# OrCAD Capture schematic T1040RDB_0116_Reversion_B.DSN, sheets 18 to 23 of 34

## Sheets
18 18 QSG PHY1: size B
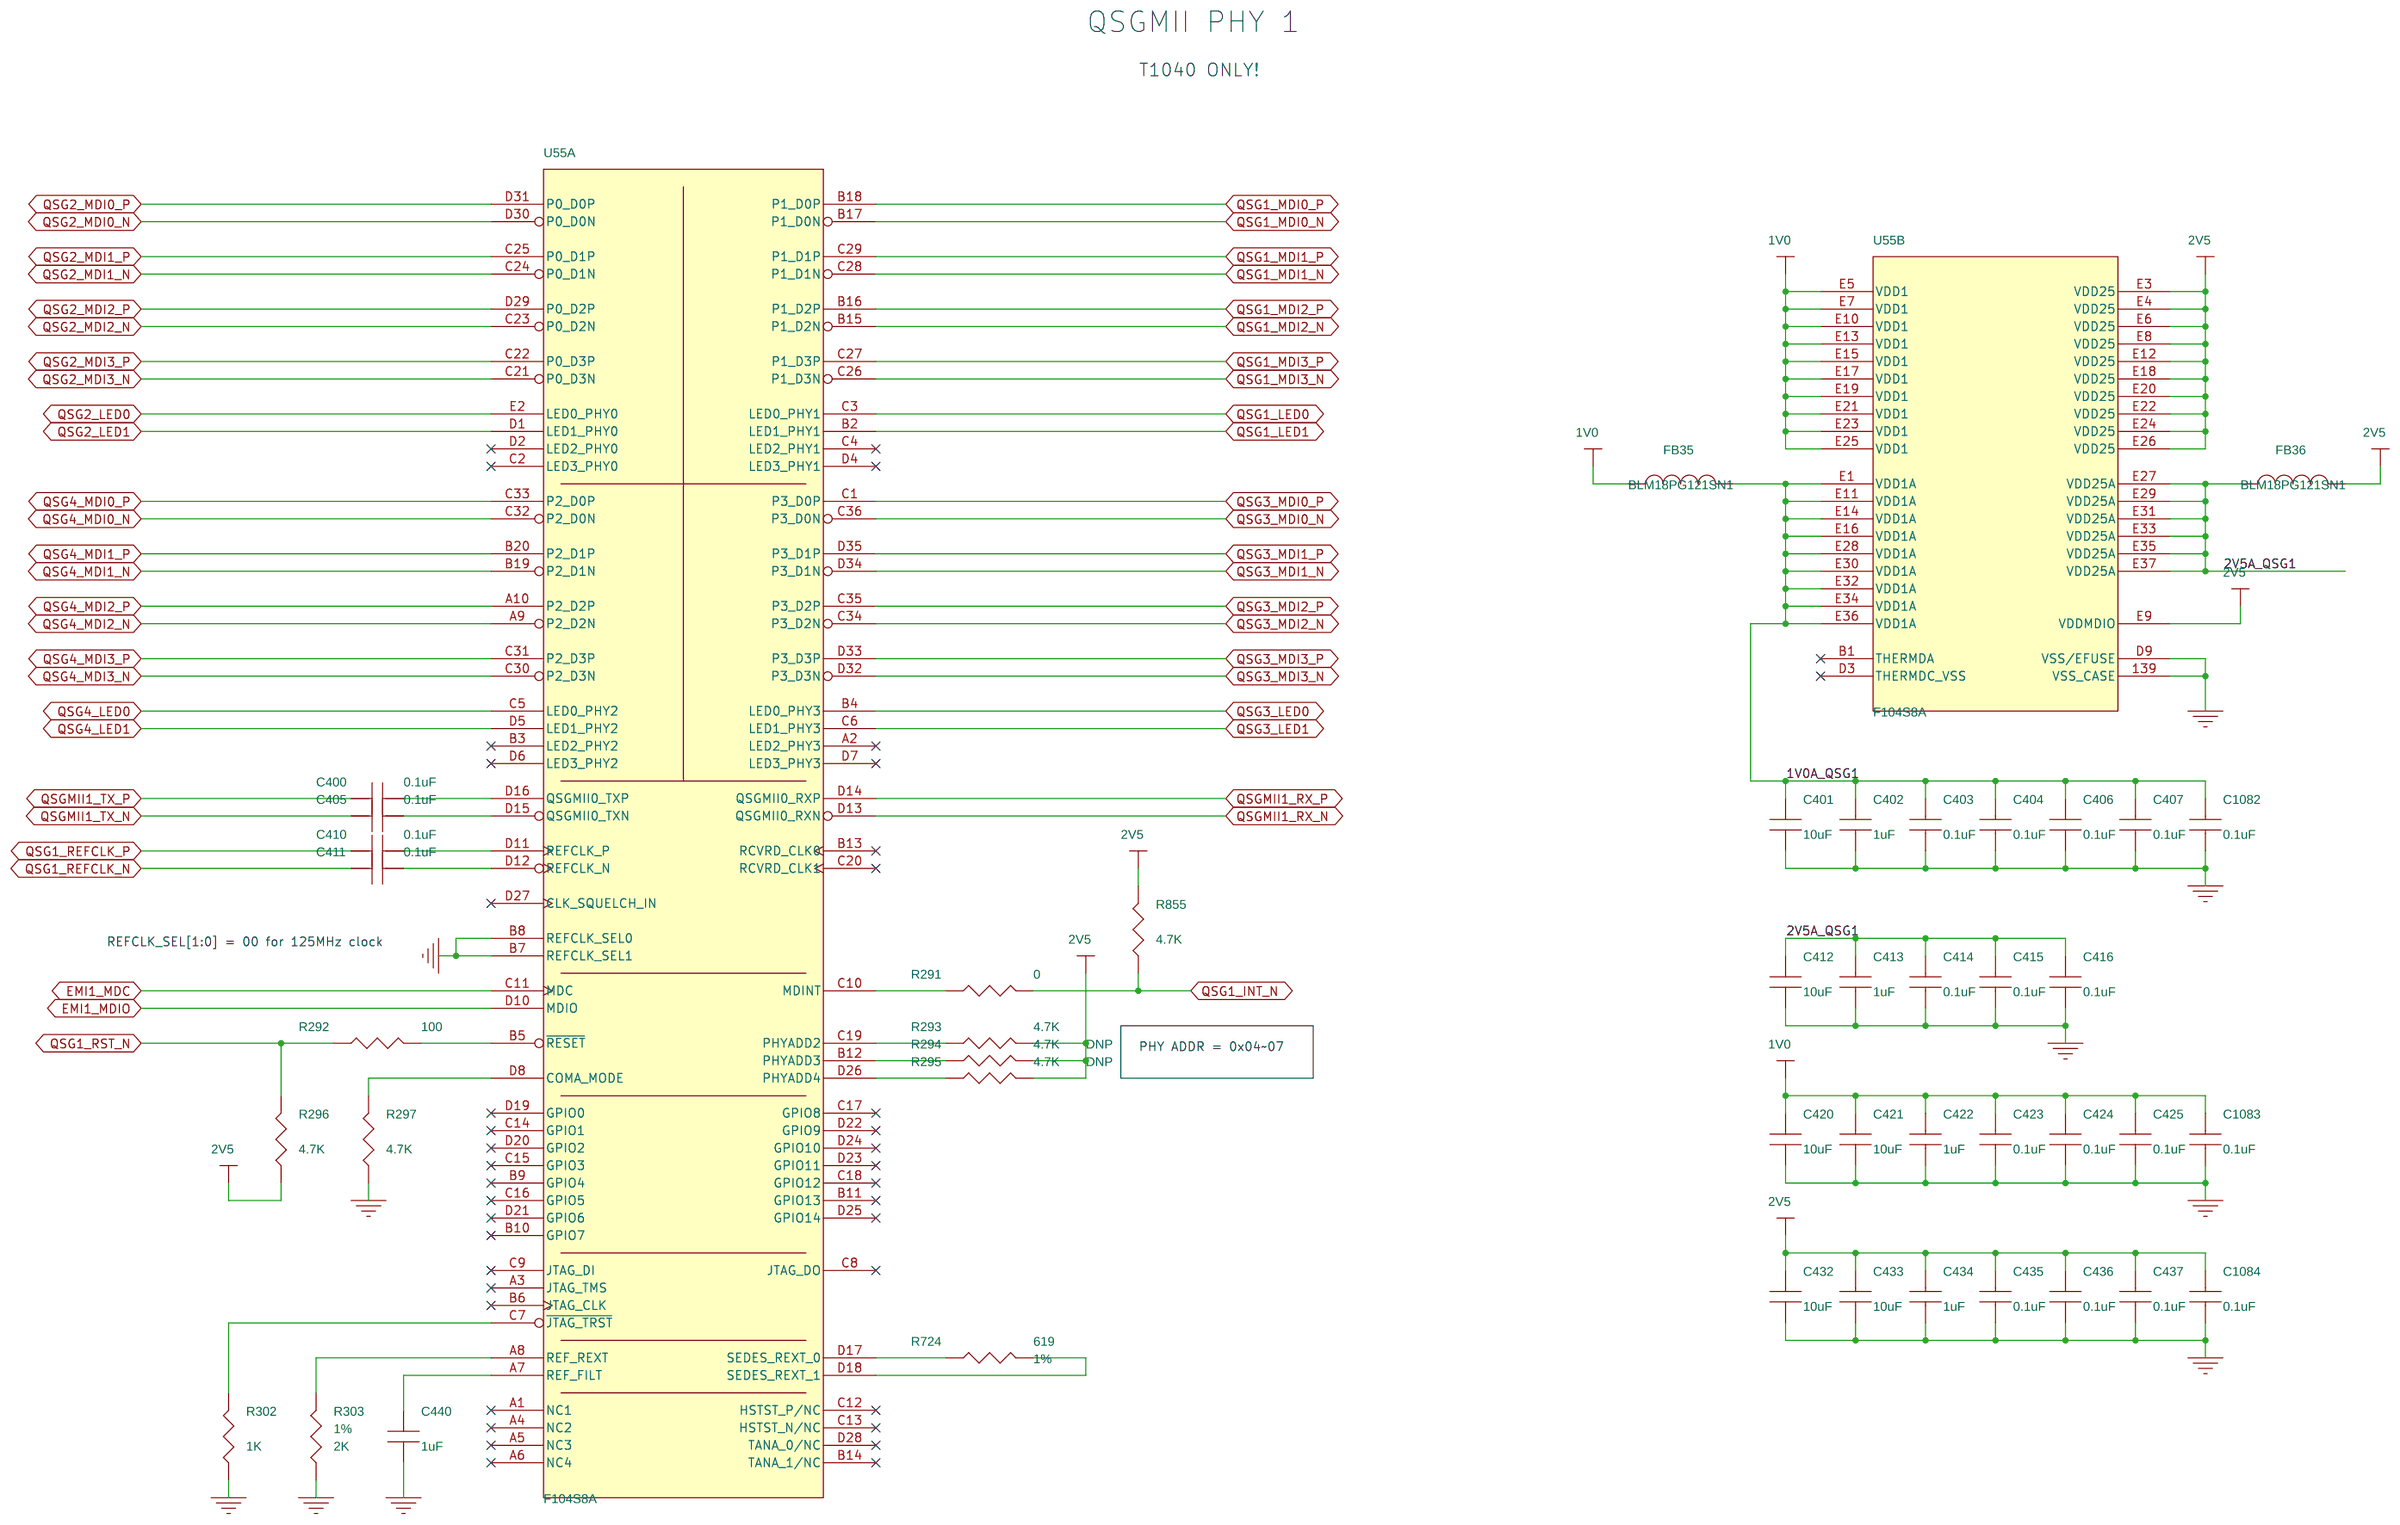
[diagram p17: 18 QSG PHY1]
19 19 QSG PHY2: size B
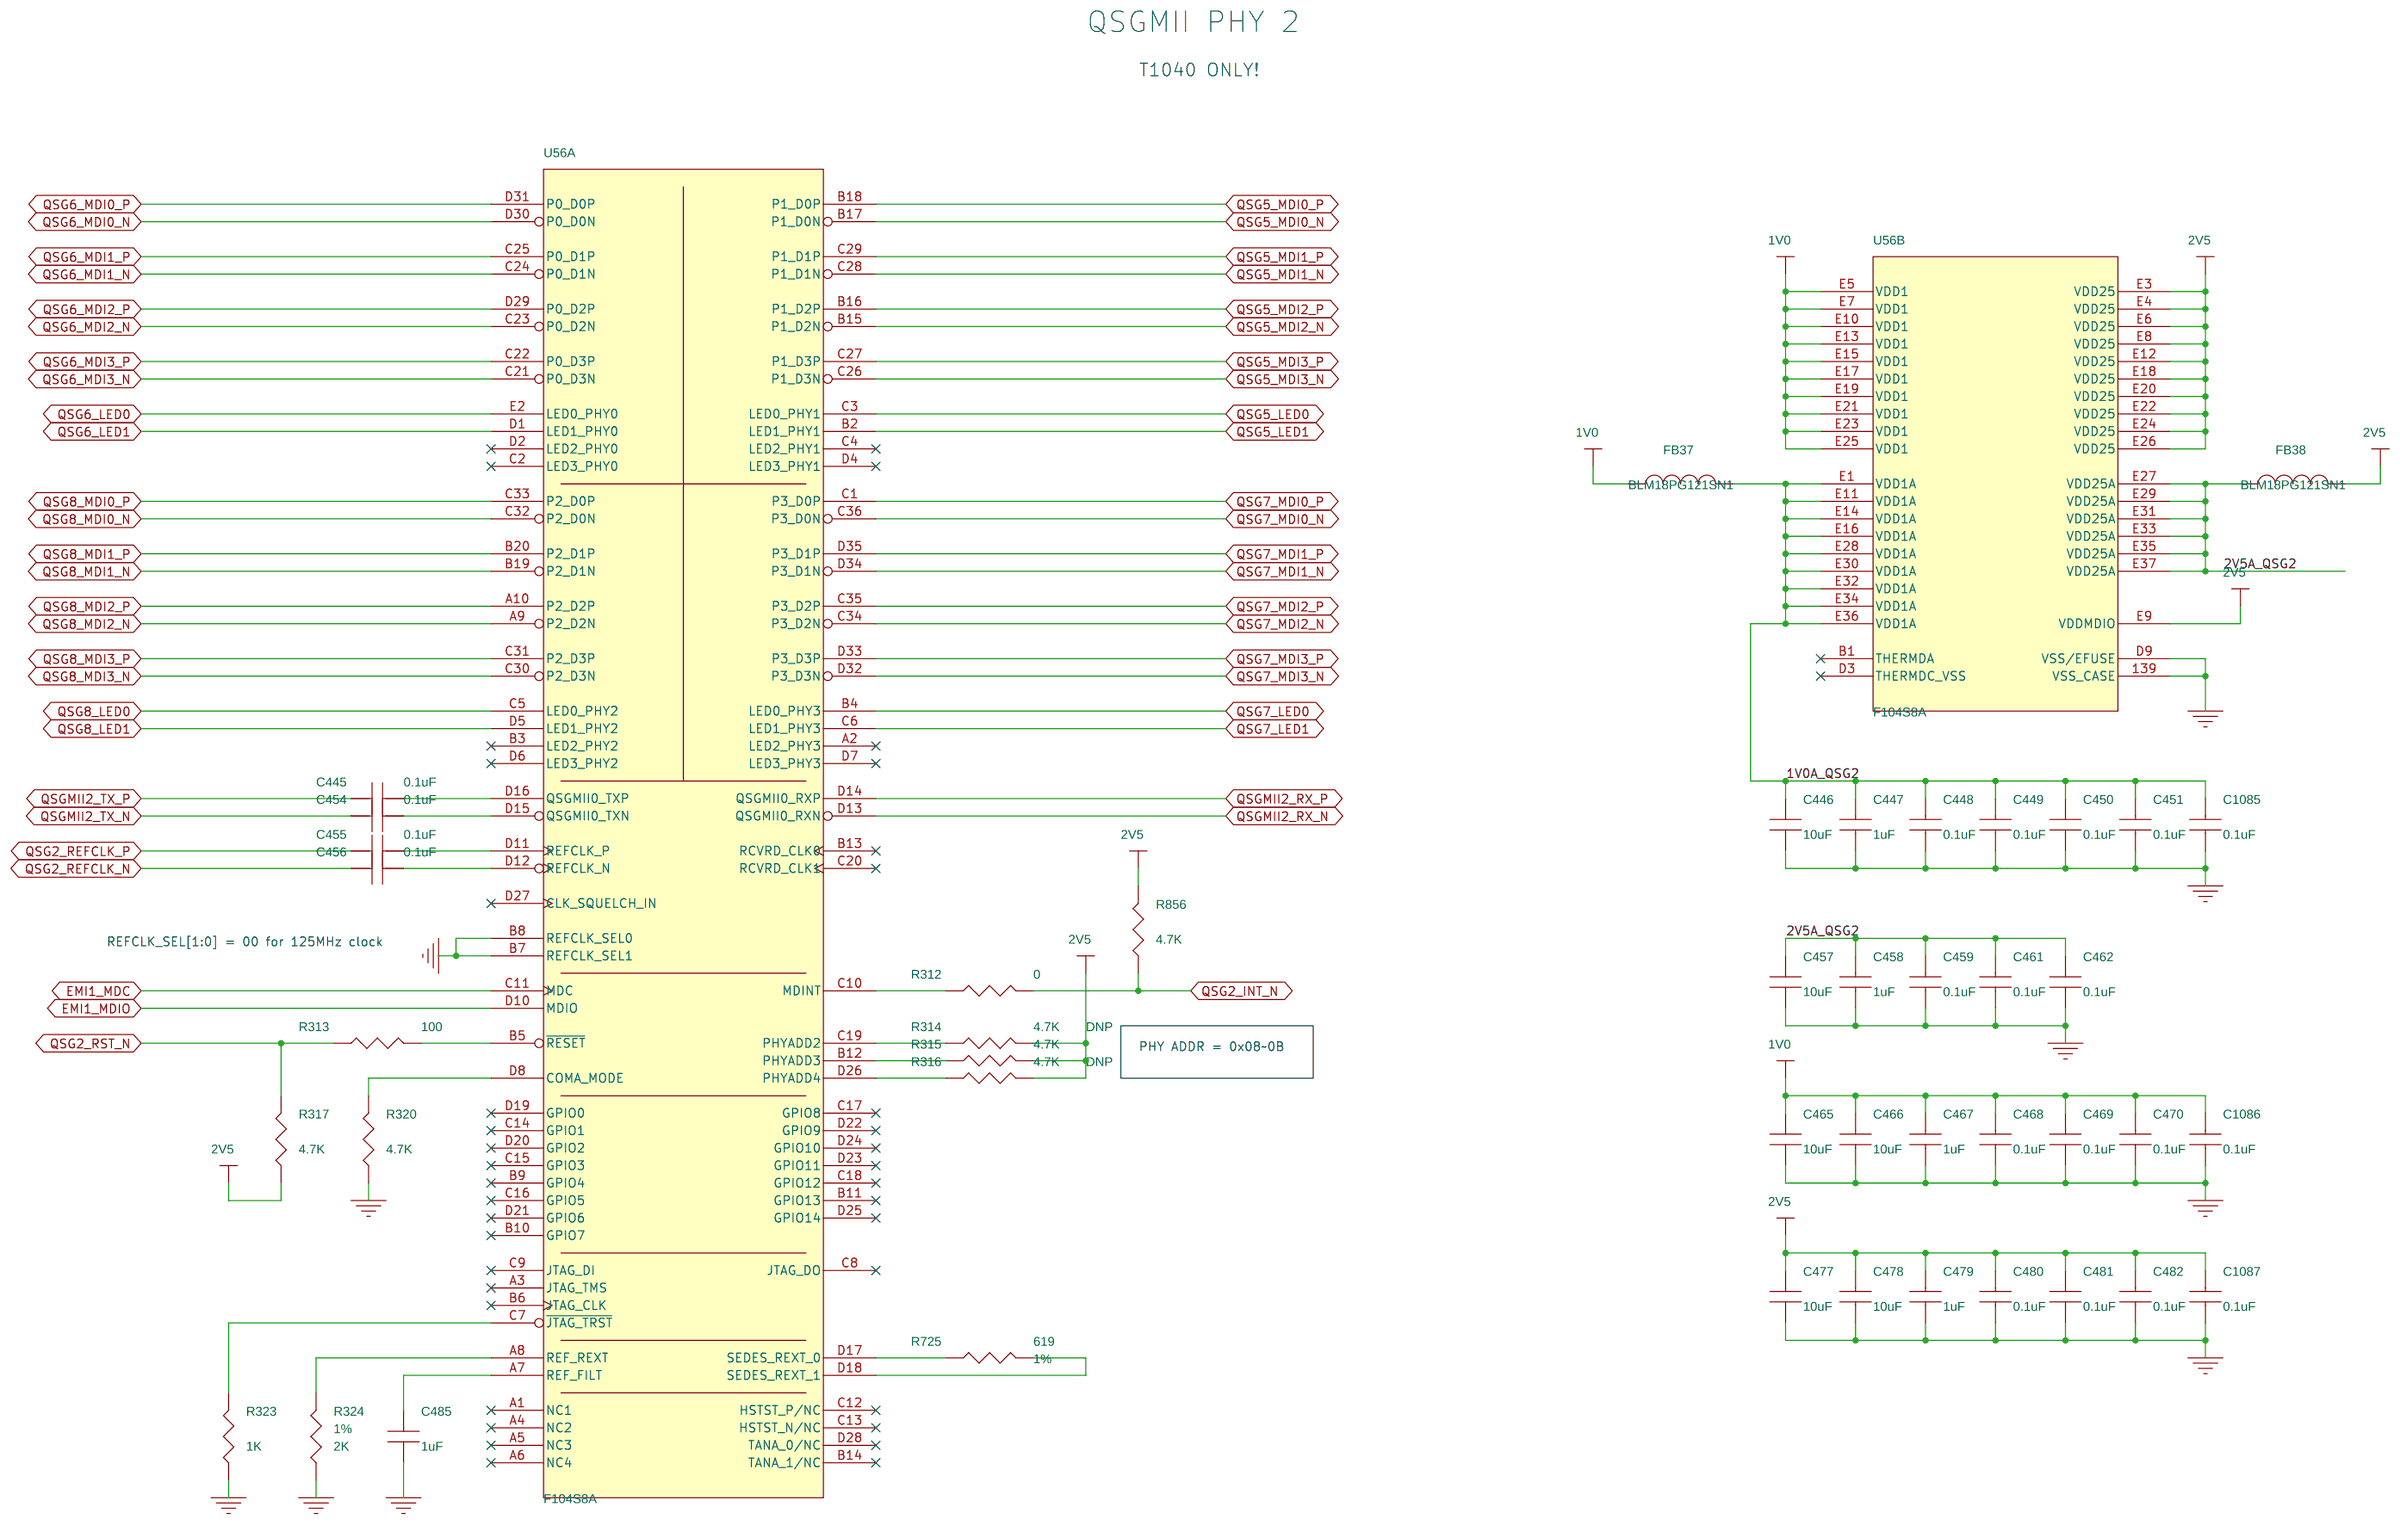
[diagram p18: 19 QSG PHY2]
20 20 QSG RJ45: size B
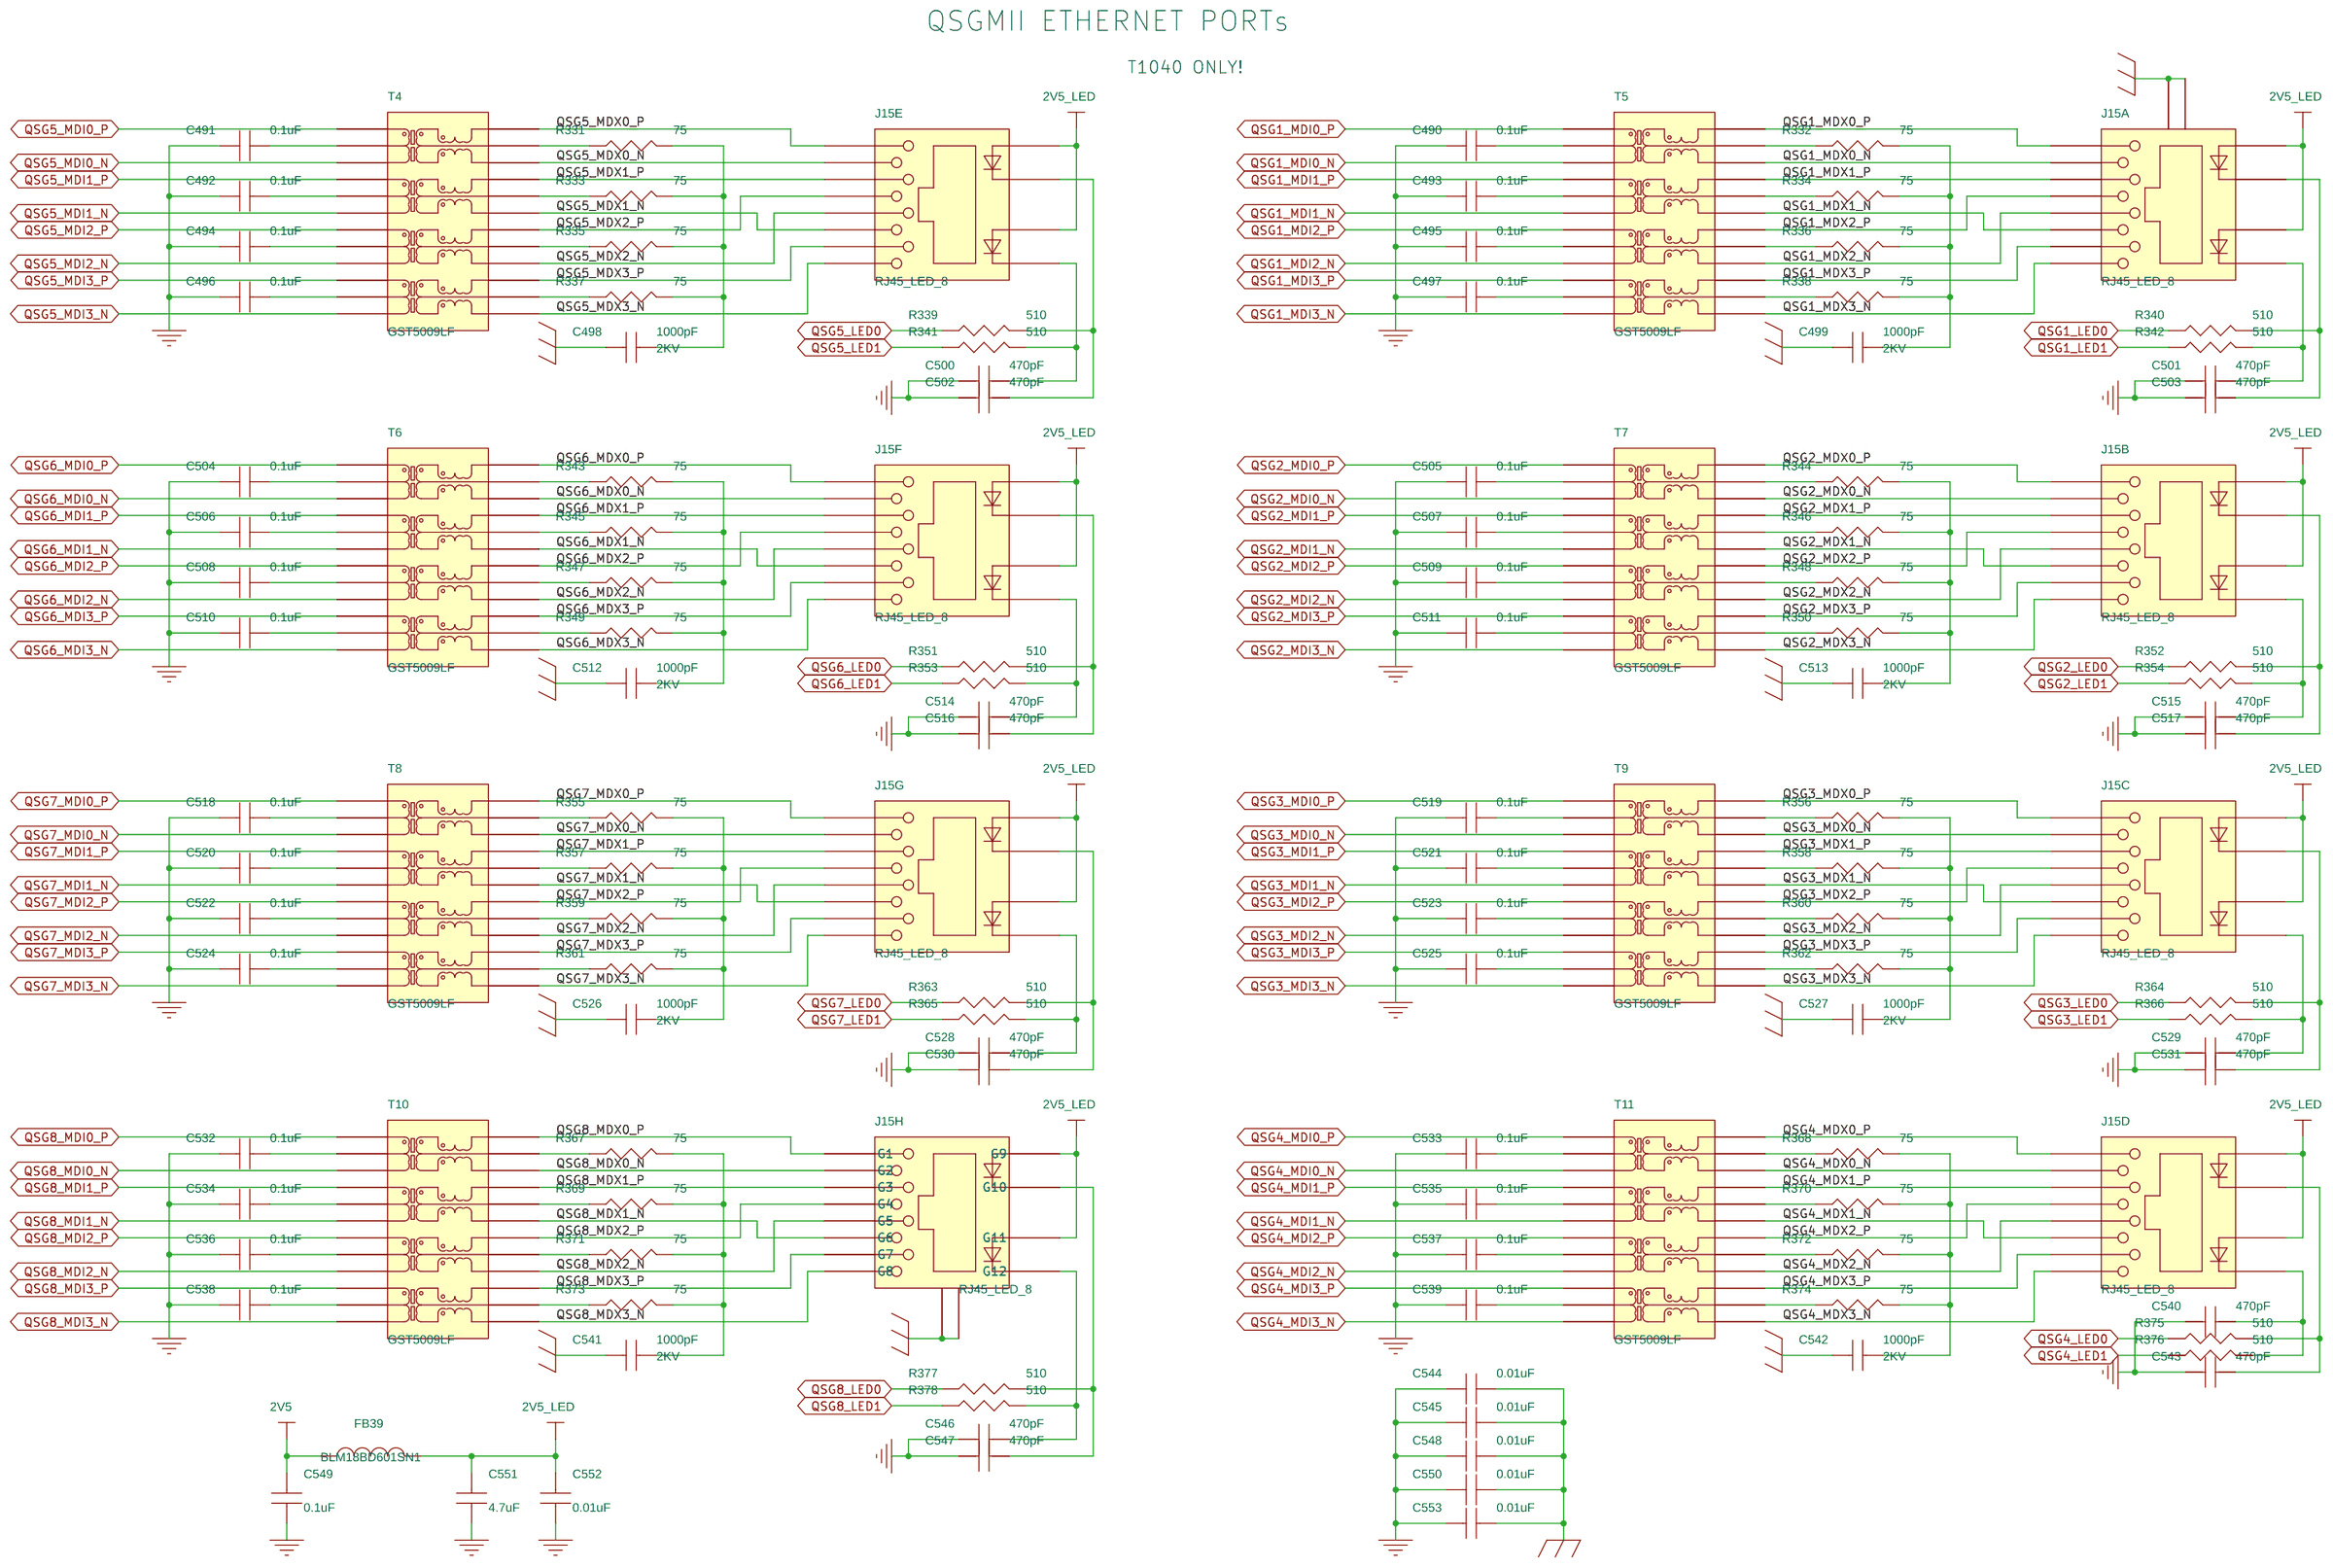
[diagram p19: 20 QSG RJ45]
21 21 XG PHY: size B
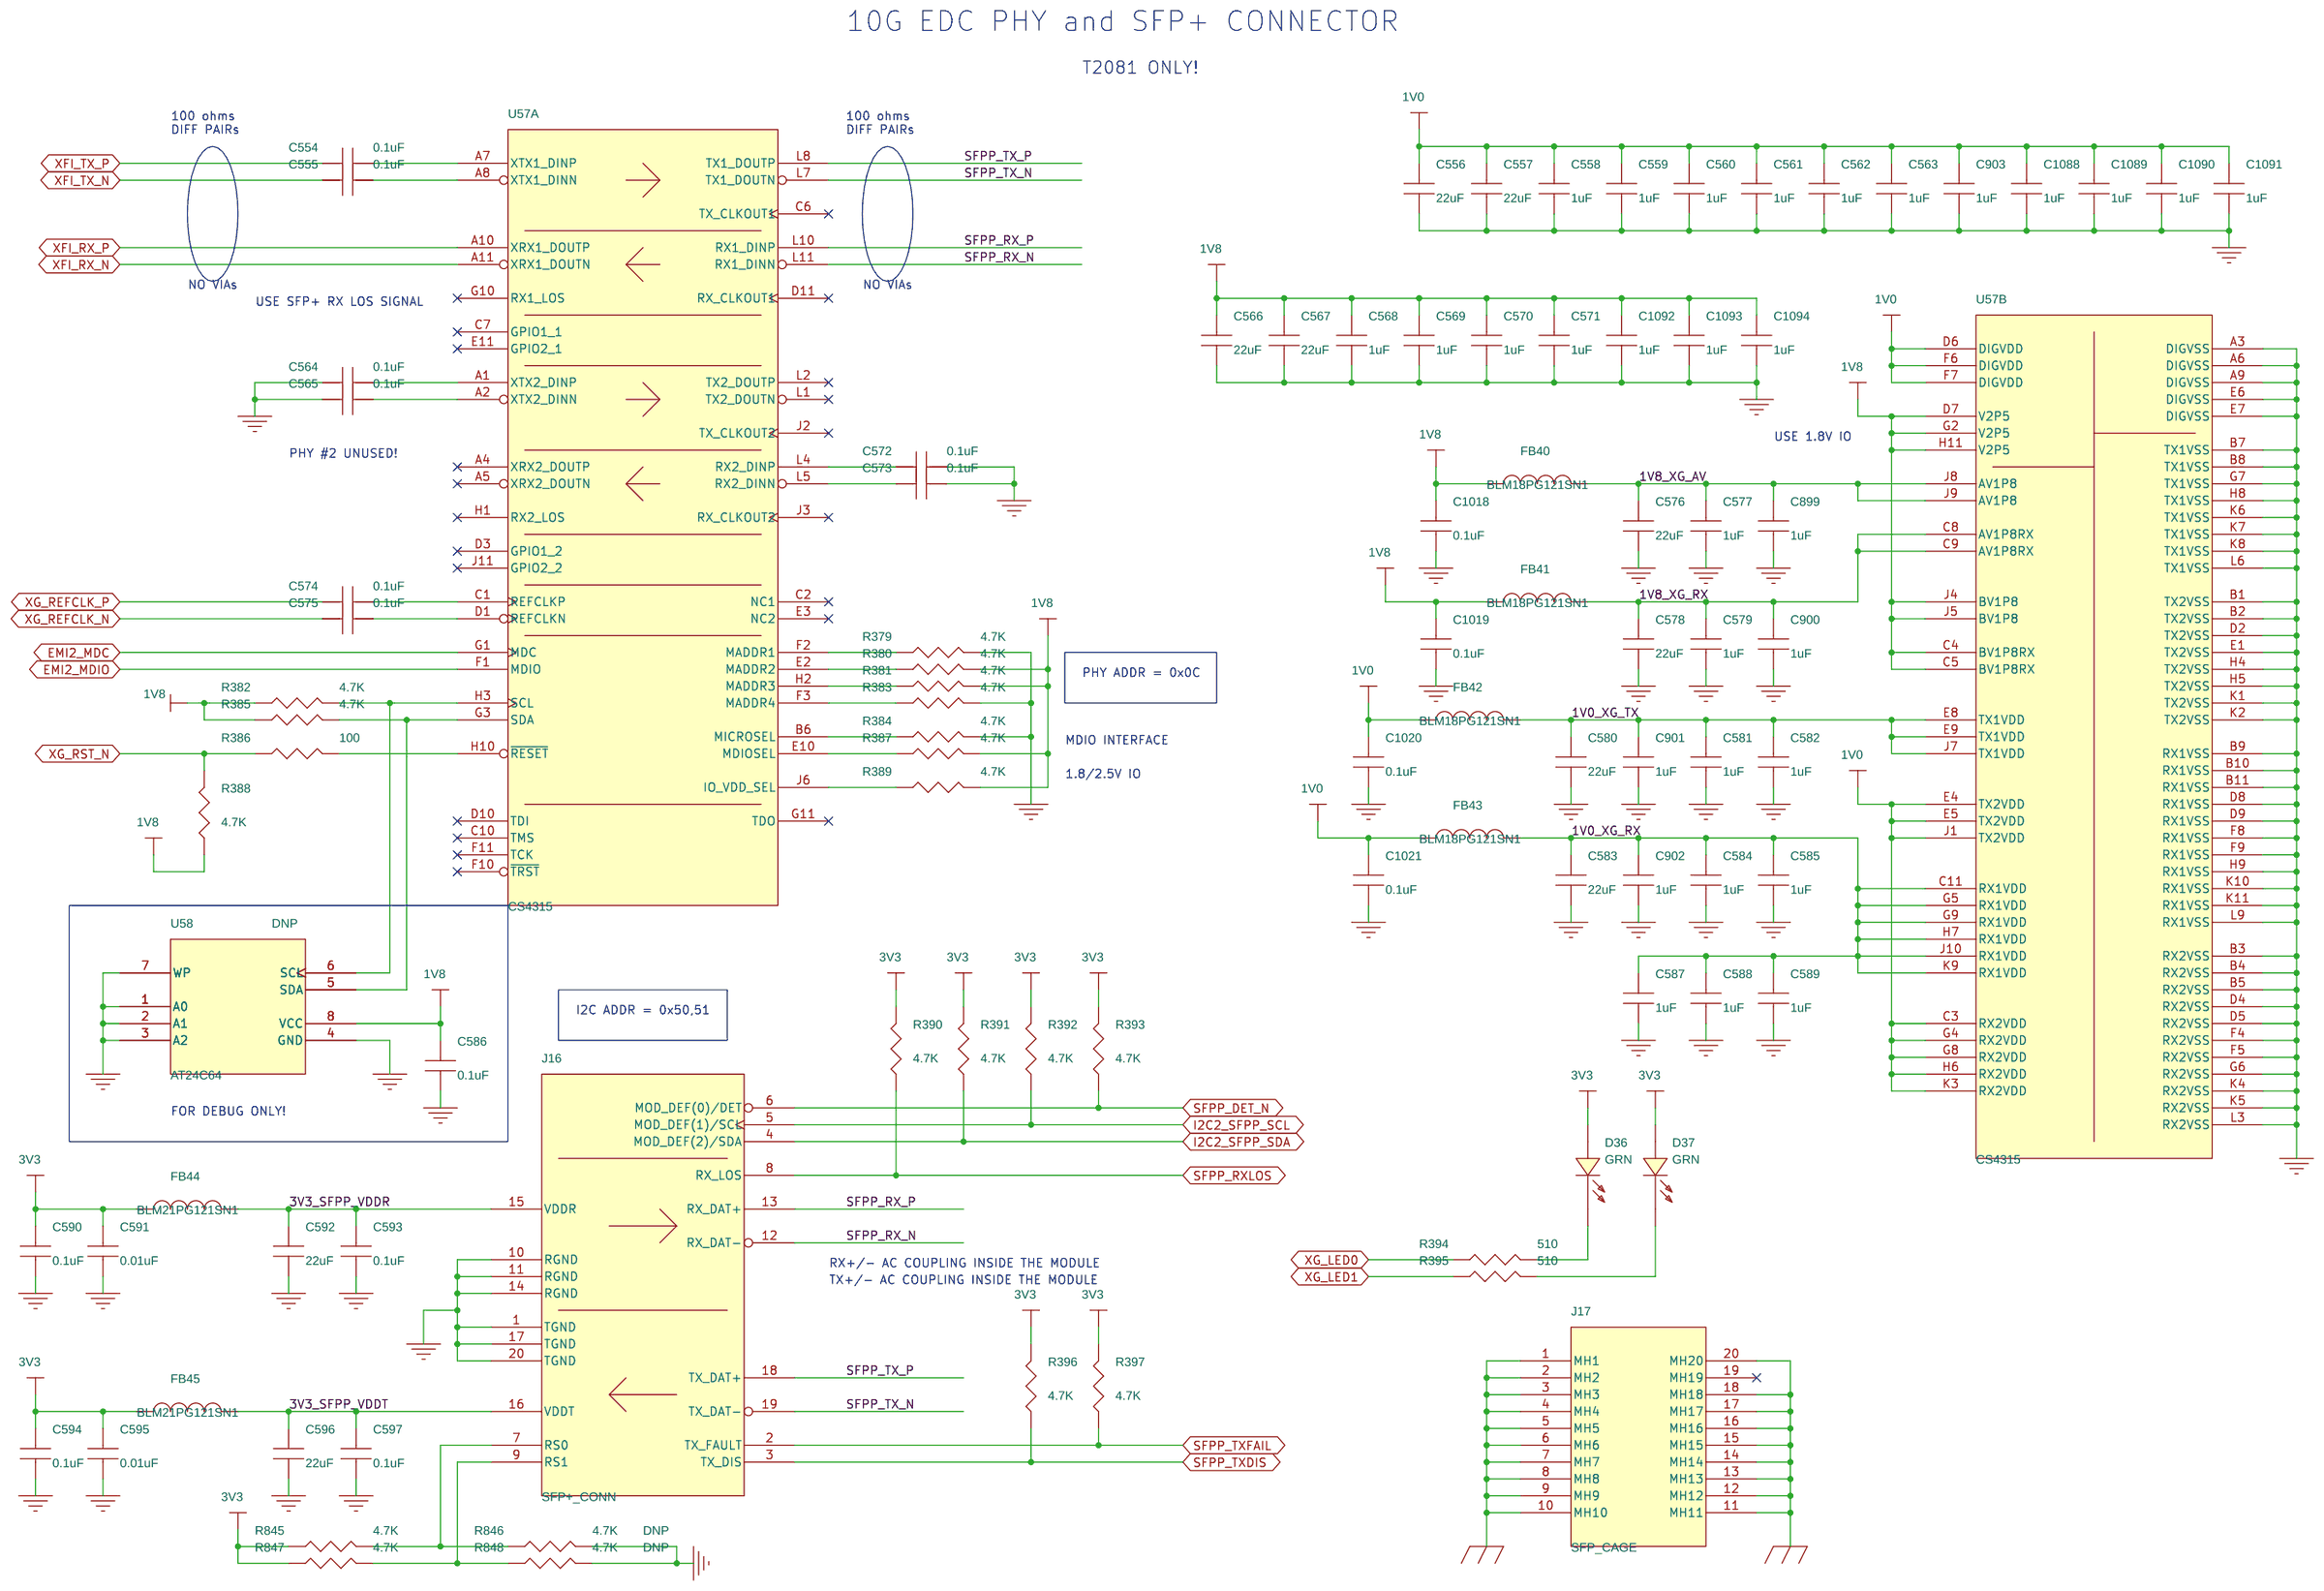
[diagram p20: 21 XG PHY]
22 22 PCIe: size B
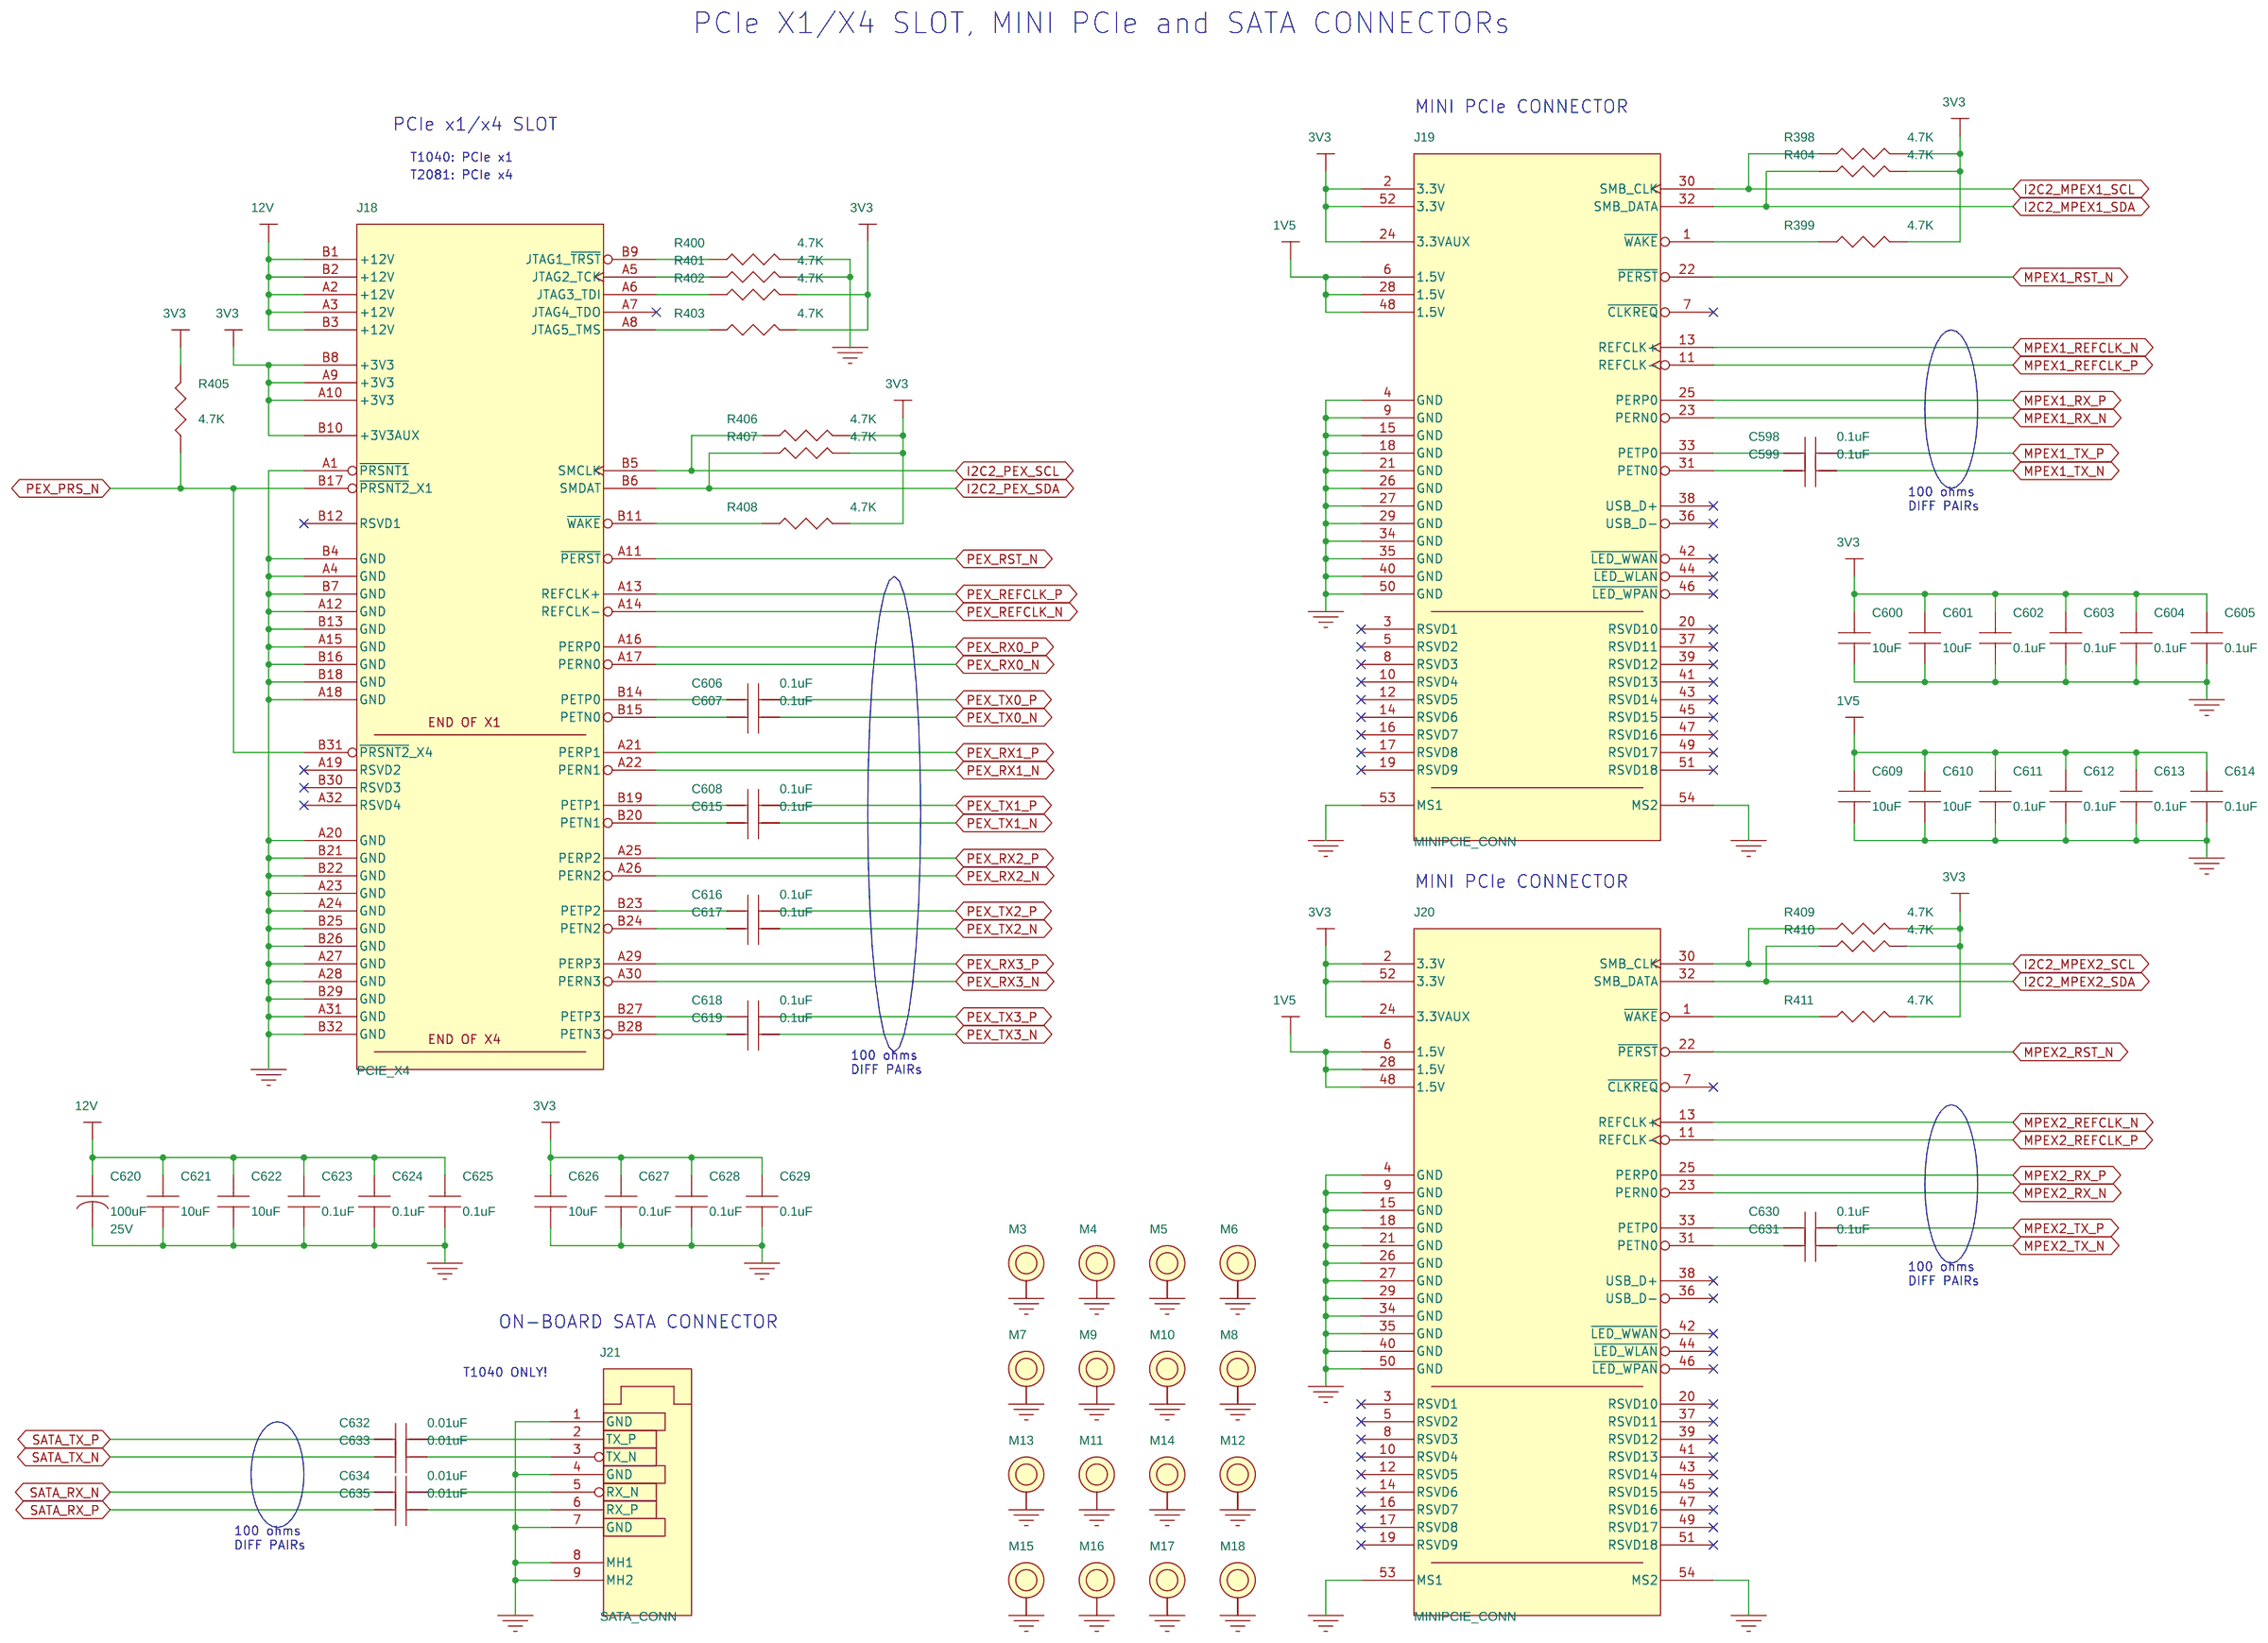
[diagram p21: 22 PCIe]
23 23 POTS1&2: size B
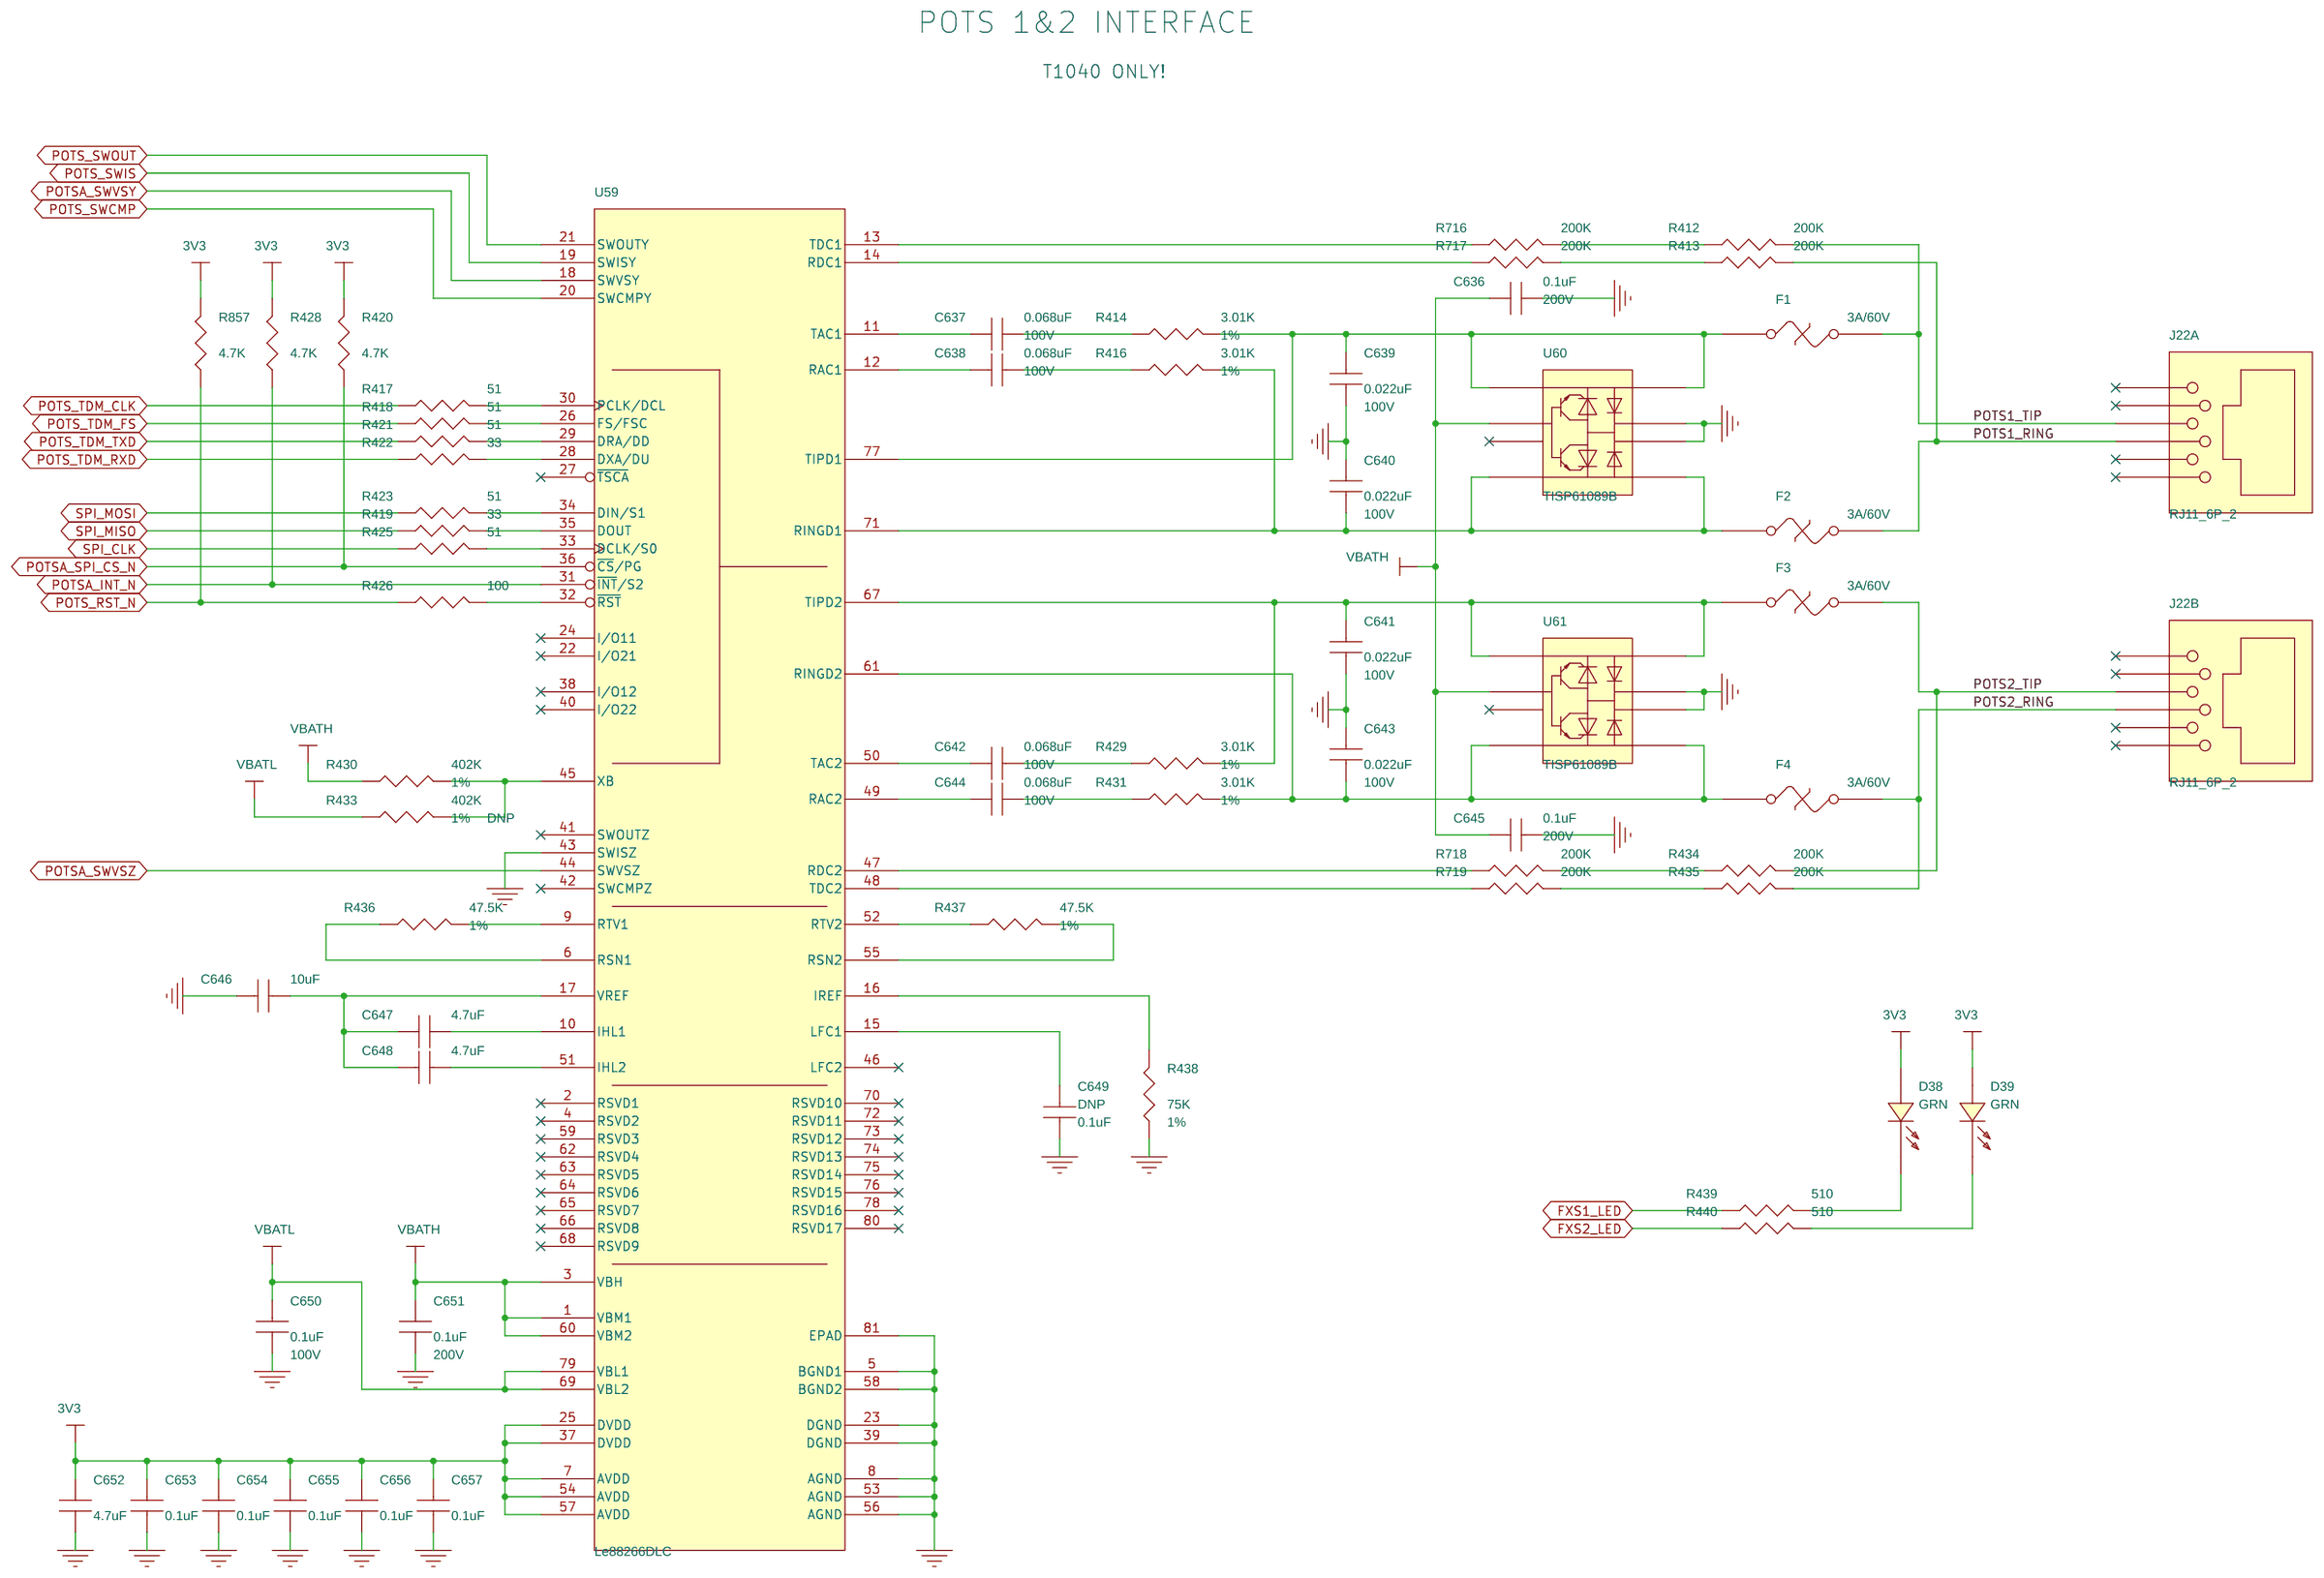
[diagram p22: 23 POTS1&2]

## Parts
sheet 18 QSG PHY1
C400  0.1uF  [0402]
C401  10uF  [0603]
C402  1uF  [0402]
C403  0.1uF  [0402]
C404  0.1uF  [0402]
C405  0.1uF  [0402]
C406  0.1uF  [0402]
C407  0.1uF  [0402]
C410  0.1uF  [0402]
C411  0.1uF  [0402]
C412  10uF  [0603]
C413  1uF  [0402]
C414  0.1uF  [0402]
C415  0.1uF  [0402]
C416  0.1uF  [0402]
C420  10uF  [0603]
C421  10uF  [0603]
C422  1uF  [0402]
C423  0.1uF  [0402]
C424  0.1uF  [0402]
C425  0.1uF  [0402]
C432  10uF  [0603]
C433  10uF  [0603]
C434  1uF  [0402]
C435  0.1uF  [0402]
C436  0.1uF  [0402]
C437  0.1uF  [0402]
C440  1uF  [0402]
C1082  0.1uF  [0402]
C1083  0.1uF  [0402]
C1084  0.1uF  [0402]
FB35  BLM18PG121SN1  [0603]
FB36  BLM18PG121SN1  [0603]
R291  0  [0402]
R292  100  [0402]
R293  4.7K  [0402]
R294  4.7K  [0402]
R295  4.7K  [0402]
R296  4.7K  [0402]
R297  4.7K  [0402]
R302  1K  [0402]
R303  2K  [0402]
R724  619  [0402]
R855  4.7K  [0402]
U55  F104S8A  [qfn_vsc8514]  (sections A,B)
sheet 19 QSG PHY2
C445  0.1uF  [0402]
C446  10uF  [0603]
C447  1uF  [0402]
C448  0.1uF  [0402]
C449  0.1uF  [0402]
C450  0.1uF  [0402]
C451  0.1uF  [0402]
C454  0.1uF  [0402]
C455  0.1uF  [0402]
C456  0.1uF  [0402]
C457  10uF  [0603]
C458  1uF  [0402]
C459  0.1uF  [0402]
C461  0.1uF  [0402]
C462  0.1uF  [0402]
C465  10uF  [0603]
C466  10uF  [0603]
C467  1uF  [0402]
C468  0.1uF  [0402]
C469  0.1uF  [0402]
C470  0.1uF  [0402]
C477  10uF  [0603]
C478  10uF  [0603]
C479  1uF  [0402]
C480  0.1uF  [0402]
C481  0.1uF  [0402]
C482  0.1uF  [0402]
C485  1uF  [0402]
C1085  0.1uF  [0402]
C1086  0.1uF  [0402]
C1087  0.1uF  [0402]
FB37  BLM18PG121SN1  [0603]
FB38  BLM18PG121SN1  [0603]
R312  0  [0402]
R313  100  [0402]
R314  4.7K  [0402]
R315  4.7K  [0402]
R316  4.7K  [0402]
R317  4.7K  [0402]
R320  4.7K  [0402]
R323  1K  [0402]
R324  2K  [0402]
R725  619  [0402]
R856  4.7K  [0402]
U56  F104S8A  [qfn_vsc8514]  (sections A,B)
sheet 20 QSG RJ45
C490  0.1uF  [0402]
C491  0.1uF  [0402]
C492  0.1uF  [0402]
C493  0.1uF  [0402]
C494  0.1uF  [0402]
C495  0.1uF  [0402]
C496  0.1uF  [0402]
C497  0.1uF  [0402]
C498  1000pF  [1206]
C499  1000pF  [1206]
C500  470pF  [0402]
C501  470pF  [0402]
C502  470pF  [0402]
C503  470pF  [0402]
C504  0.1uF  [0402]
C505  0.1uF  [0402]
C506  0.1uF  [0402]
C507  0.1uF  [0402]
C508  0.1uF  [0402]
C509  0.1uF  [0402]
C510  0.1uF  [0402]
C511  0.1uF  [0402]
C512  1000pF  [1206]
C513  1000pF  [1206]
C514  470pF  [0402]
C515  470pF  [0402]
C516  470pF  [0402]
C517  470pF  [0402]
C518  0.1uF  [0402]
C519  0.1uF  [0402]
C520  0.1uF  [0402]
C521  0.1uF  [0402]
C522  0.1uF  [0402]
C523  0.1uF  [0402]
C524  0.1uF  [0402]
C525  0.1uF  [0402]
C526  1000pF  [1206]
C527  1000pF  [1206]
C528  470pF  [0402]
C529  470pF  [0402]
C530  470pF  [0402]
C531  470pF  [0402]
C532  0.1uF  [0402]
C533  0.1uF  [0402]
C534  0.1uF  [0402]
C535  0.1uF  [0402]
C536  0.1uF  [0402]
C537  0.1uF  [0402]
C538  0.1uF  [0402]
C539  0.1uF  [0402]
C540  470pF  [0402]
C541  1000pF  [1206]
C542  1000pF  [1206]
C543  470pF  [0402]
C544  0.01uF  [0402]
C545  0.01uF  [0402]
C546  470pF  [0402]
C547  470pF  [0402]
C548  0.01uF  [0402]
C549  0.1uF  [0402]
C550  0.01uF  [0402]
C551  4.7uF  [0603]
C552  0.01uF  [0402]
C553  0.01uF  [0402]
FB39  BLM18BD601SN1  [0603]
J15  RJ45_LED_8  [con_rj45_2x4_led]  (sections A,B,C,D,E,F,G,H)
R331  75  [0603]
R332  75  [0603]
R333  75  [0603]
R334  75  [0603]
R335  75  [0603]
R336  75  [0603]
R337  75  [0603]
R338  75  [0603]
R339  510  [0402]
R340  510  [0402]
R341  510  [0402]
R342  510  [0402]
R343  75  [0603]
R344  75  [0603]
R345  75  [0603]
R346  75  [0603]
R347  75  [0603]
R348  75  [0603]
R349  75  [0603]
R350  75  [0603]
R351  510  [0402]
R352  510  [0402]
R353  510  [0402]
R354  510  [0402]
R355  75  [0603]
R356  75  [0603]
R357  75  [0603]
R358  75  [0603]
R359  75  [0603]
R360  75  [0603]
R361  75  [0603]
R362  75  [0603]
R363  510  [0402]
R364  510  [0402]
R365  510  [0402]
R366  510  [0402]
R367  75  [0603]
R368  75  [0603]
R369  75  [0603]
R370  75  [0603]
R371  75  [0603]
R372  75  [0603]
R373  75  [0603]
R374  75  [0603]
R375  510  [0402]
R376  510  [0402]
R377  510  [0402]
R378  510  [0402]
T4  GST5009LF  [mag_gst5009]
T5  GST5009LF  [mag_gst5009]
T6  GST5009LF  [mag_gst5009]
T7  GST5009LF  [mag_gst5009]
T8  GST5009LF  [mag_gst5009]
T9  GST5009LF  [mag_gst5009]
T10  GST5009LF  [mag_gst5009]
T11  GST5009LF  [mag_gst5009]
sheet 21 XG PHY
C554  0.1uF  [0402]
C555  0.1uF  [0402]
C556  22uF  [0805]
C557  22uF  [0805]
C558  1uF  [0402o]
C559  1uF  [0402o]
C560  1uF  [0402o]
C561  1uF  [0402o]
C562  1uF  [0402o]
C563  1uF  [0402o]
C564  0.1uF  [0402]
C565  0.1uF  [0402]
C566  22uF  [0805]
C567  22uF  [0805]
C568  1uF  [0402o]
C569  1uF  [0402o]
C570  1uF  [0402o]
C571  1uF  [0402o]
C572  0.1uF  [0402]
C573  0.1uF  [0402]
C574  0.1uF  [0402]
C575  0.1uF  [0402]
C576  22uF  [0805]
C577  1uF  [0402o]
C578  22uF  [0805]
C579  1uF  [0402o]
C580  22uF  [0805]
C581  1uF  [0402o]
C582  1uF  [0402o]
C583  22uF  [0805]
C584  1uF  [0402o]
C585  1uF  [0402o]
C586  0.1uF  [0402]
C587  1uF  [0402o]
C588  1uF  [0402o]
C589  1uF  [0402o]
C590  0.1uF  [0402]
C591  0.01uF  [0402]
C592  22uF  [0805]
C593  0.1uF  [0402]
C594  0.1uF  [0402]
C595  0.01uF  [0402]
C596  22uF  [0805]
C597  0.1uF  [0402]
C899  1uF  [0402o]
C900  1uF  [0402o]
C901  1uF  [0402o]
C902  1uF  [0402o]
C903  1uF  [0402o]
C1018  0.1uF  [0402]
C1019  0.1uF  [0402]
C1020  0.1uF  [0402]
C1021  0.1uF  [0402]
C1088  1uF  [0402o]
C1089  1uF  [0402o]
C1090  1uF  [0402o]
C1091  1uF  [0402o]
C1092  1uF  [0402o]
C1093  1uF  [0402o]
C1094  1uF  [0402o]
D36  GRN  [led_pm_1s]
D37  GRN  [led_pm_1s]
FB40  BLM18PG121SN1  [0603]
FB41  BLM18PG121SN1  [0603]
FB42  BLM18PG121SN1  [0603]
FB43  BLM18PG121SN1  [0603]
FB44  BLM21PG121SN1  [0805]
FB45  BLM21PG121SN1  [0805]
J16  SFP+_CONN  [con_sfp]
J17  SFP_CAGE  [con_sfp_cage]
R379  4.7K  [0402o]
R380  4.7K  [0402o]
R381  4.7K  [0402o]
R382  4.7K  [0402]
R383  4.7K  [0402o]
R384  4.7K  [0402o]
R385  4.7K  [0402]
R386  100  [0402]
R387  4.7K  [0402o]
R388  4.7K  [0402]
R389  4.7K  [0402o]
R390  4.7K  [0402]
R391  4.7K  [0402]
R392  4.7K  [0402]
R393  4.7K  [0402]
R394  510  [0402]
R395  510  [0402]
R396  4.7K  [0402]
R397  4.7K  [0402]
R845  4.7K  [0402]
R846  4.7K  [0402]
R847  4.7K  [0402]
R848  4.7K  [0402]
U57  CS4315  [bga_p100_121]  (sections A,B)
U58  AT24C64  [tssop_8]
sheet 22 PCIe
C598  0.1uF  [0402]
C599  0.1uF  [0402]
C600  10uF  [0603]
C601  10uF  [0603]
C602  0.1uF  [0402]
C603  0.1uF  [0402]
C604  0.1uF  [0402]
C605  0.1uF  [0402]
C606  0.1uF  [0402]
C607  0.1uF  [0402]
C608  0.1uF  [0402]
C609  10uF  [0603]
C610  10uF  [0603]
C611  0.1uF  [0402]
C612  0.1uF  [0402]
C613  0.1uF  [0402]
C614  0.1uF  [0402]
C615  0.1uF  [0402]
C616  0.1uF  [0402]
C617  0.1uF  [0402]
C618  0.1uF  [0402]
C619  0.1uF  [0402]
C620  100uF  [cape_b6d3]
C621  10uF  [1206]
C622  10uF  [1206]
C623  0.1uF  [0603]
C624  0.1uF  [0603]
C625  0.1uF  [0603]
C626  10uF  [0603]
C627  0.1uF  [0402]
C628  0.1uF  [0402]
C629  0.1uF  [0402]
C630  0.1uF  [0402]
C631  0.1uF  [0402]
C632  0.01uF  [0402]
C633  0.01uF  [0402]
C634  0.01uF  [0402]
C635  0.01uF  [0402]
J18  PCIE_X4  [con_pex4]
J19  MINIPCIE_CONN  [con_minipcie]
J20  MINIPCIE_CONN  [con_minipcie]
J21  SATA_CONN  [con_sata]
M3  MH  [mh_580s340p]
M4  MH  [mh_580s340p]
M5  MH  [mh_580s340p]
M6  MH  [mh_580s340p]
M7  MH  [mh_580s340p]
M8  MH  [mh_580s340p]
M9  MH  [mh_580s340p]
M10  MH  [mh_580s340p]
M11  MH  [mh_580s340p]
M12  MH  [mh_580s340p]
M13  MH  [mh_580s340p]
M14  MH  [mh_580s340p]
M15  MH  [mh_580s340p]
M16  MH  [mh_580s340p]
M17  MH  [mh_580s340p]
M18  MH  [mh_580s340p]
R398  4.7K  [0402]
R399  4.7K  [0402]
R400  4.7K  [0402]
R401  4.7K  [0402]
R402  4.7K  [0402]
R403  4.7K  [0402]
R404  4.7K  [0402]
R405  4.7K  [0402]
R406  4.7K  [0402]
R407  4.7K  [0402]
R408  4.7K  [0402]
R409  4.7K  [0402]
R410  4.7K  [0402]
R411  4.7K  [0402]
sheet 23 POTS1&2
C636  0.1uF  [1206]
C637  0.068uF  [0805]
C638  0.068uF  [0805]
C639  0.022uF  [0805]
C640  0.022uF  [0805]
C641  0.022uF  [0805]
C642  0.068uF  [0805]
C643  0.022uF  [0805]
C644  0.068uF  [0805]
C645  0.1uF  [1206]
C646  10uF  [0603]
C647  4.7uF  [0603]
C648  4.7uF  [0603]
C649  0.1uF  [0402]
C650  0.1uF  [1206]
C651  0.1uF  [1206]
C652  4.7uF  [0603]
C653  0.1uF  [0402]
C654  0.1uF  [0402]
C655  0.1uF  [0402]
C656  0.1uF  [0402]
C657  0.1uF  [0402]
D38  GRN  [led_pm_1s]
D39  GRN  [led_pm_1s]
F1  3A/60V  [ptc_sm013]
F2  3A/60V  [ptc_sm013]
F3  3A/60V  [ptc_sm013]
F4  3A/60V  [ptc_sm013]
J22  RJ11_6P_2  [con_rj11_6p_2x1]  (sections A,B)
R412  200K  [1206]
R413  200K  [1206]
R414  3.01K  [0805]
R416  3.01K  [0805]
R417  51  [0402]
R418  51  [0402]
R419  33  [0402]
R420  4.7K  [0402]
R421  51  [0402]
R422  33  [0402]
R423  51  [0402]
R425  51  [0402]
R426  100  [0402]
R428  4.7K  [0402]
R429  3.01K  [0805]
R430  402K  [0805]
R431  3.01K  [0805]
R433  402K  [0805]
R434  200K  [1206]
R435  200K  [1206]
R436  47.5K  [0402]
R437  47.5K  [0402]
R438  75K  [0402]
R439  510  [0402]
R440  510  [0402]
R716  200K  [1206]
R717  200K  [1206]
R718  200K  [1206]
R719  200K  [1206]
R857  4.7K  [0402]
U59  Le88266DLC  [qfp_p065_80_e780]
U60  TISP61089B  [so_8]
U61  TISP61089B  [so_8]

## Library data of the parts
C400 C403-C407 C410 C411 C414-C416 C423-C425 C435-C437 C445 C448-C451 C454-C456 C459 C461 C462 C468-C470 C480-C482 C490-C497 C504-C511 C518-C525 C532-C539 C549 C554 C555 C564 C565 C572-C575 C586 C590 C593 C594 C597-C599 C602-C608 C611-C619 C627-C631 C653-C657 C1018-C1021 C1082-C1087 = CAP: VOLTAGE: 16V
C401 C402 C412 C413 C420-C422 C432-C434 C440 C446 C447 C457 C458 C465-C467 C477-C479 C485 C551 C556-C563 C566-C571 C576-C585 C587-C589 C592 C596 C600 C601 C609 C610 C626 C646-C648 C652 C899-C903 C1088-C1094 = CAP: VOLTAGE: 6.3V
FB35-FB45 = BEAD: Vendor: Murata
R291-R293 R296 R297 R302 R312 R313 R315 R317 R320 R323 R331-R413 R417-R423 R425 R426 R428 R434 R435 R439 R440 R716-R719 R845 R847 R855-R857 = RES: TOL: 5%
R294 R295 R314 R316 R846 R848 = RES: BOM_IGNORE: DNP; TOL: 5%
R303 R324 R414 R416 R429-R431 R436-R438 R724 R725 = RES: TOL: 1%
U55 U56 = VSC8514: TYPE: IC; Vendor: Freescale
C498 C499 C512 C513 C526 C527 C541 C542 = CAP: VOLTAGE: 2KV
C500-C503 C514-C517 C528-C531 C540 C543 C546 C547 = CAP: VOLTAGE: 50V
C544 C545 C548 C550 C552 C553 C591 C595 C621-C625 C632-C635 = CAP: VOLTAGE: 25V
J15 = RJ45_LED_8: MPN: 10118077-510B010LF; TYPE: CON; Vendor: FCI
T4-T11 = GST5009LF: TYPE: XFMR; Vendor: Bothhand
D36-D39 = LED: MPN: L-96A8YVP/1GD/TG-0L; Vendor: Kingbrignt
J16 = SFP+_CONN: MPN: 3S1020C3-011-7F; TYPE: CON; Vendor: Foxconn
J17 = SFP_CAGE: MPN: 3S000000-74-4F; TYPE: CON; Vendor: Foxconn
U57 = CS4315: TYPE: IC; Vendor: Cortina
U58 = EEPROM-I2C: BOM_IGNORE: DNP; MPN: AT24C64C-SSHL-B; TYPE: IC; Vendor: Atmel
C620 = CAP_E: TYPE: CAP; VOLTAGE: 25V
J18 = PCIE_X4: MPN: 87715-9100; TYPE: CON; Vendor: MOLEX
J19 J20 = MINIPCIE_CONN: MPN: 0717A01A68C; TYPE: CON; Vendor: CONCRAFT
J21 = SATA_CONN: MPN: 97-0901HB-7W-R; TYPE: CON; Vendor: Astron
M3-M18 = MH: MPN: 071CAAAZ68B; TYPE: CON; Vendor: CONCRAFT
C636 C645 C651 = CAP: VOLTAGE: 200V
C637-C644 C650 = CAP: VOLTAGE: 100V
C649 = CAP: BOM_IGNORE: DNP; VOLTAGE: 16V
F1-F4 = PTC: MPN: MF-SM013/250V; Vendor: BOURNS
J22 = RJ11_6P_2: MPN: 8266-B01-R; TYPE: CON; Vendor: XMULTIPLE
R433 = RES: BOM_IGNORE: DNP; TOL: 1%
U59 = Le88266DLC: TYPE: IC; Vendor: Microsemi
U60 U61 = TISP61089: MPN: TISP61089BDR-S; TYPE: IC; Vendor: Bourns

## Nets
1V0: C420.1 C421.1 C422.1 C423.1 C424.1 C425.1 C465.1 C466.1 C467.1 C468.1 C469.1 C470.1 C556.1 C557.1 C558.1 C559.1 C560.1 C561.1 C562.1 C563.1 C903.1 C1020.1 C1021.1 C1083.1 C1086.1 C1088.1 C1089.1 C1090.1 C1091.1 FB35.1 FB37.1 FB42.1 FB43.1 U55.E5(VDD1) U55.E7(VDD1) U55.E10(VDD1) U55.E13(VDD1) U55.E15(VDD1) U55.E17(VDD1) U55.E19(VDD1) U55.E21(VDD1) U55.E23(VDD1) U55.E25(VDD1) U56.E5(VDD1) U56.E7(VDD1) U56.E10(VDD1) U56.E13(VDD1) U56.E15(VDD1) U56.E17(VDD1) U56.E19(VDD1) U56.E21(VDD1) U56.E23(VDD1) U56.E25(VDD1) U57.C3(RX2VDD) U57.D6(DIGVDD) U57.E4(TX2VDD) U57.E5(TX2VDD) U57.F6(DIGVDD) U57.F7(DIGVDD) U57.G4(RX2VDD) U57.G8(RX2VDD) U57.H6(RX2VDD) U57.J1(TX2VDD) U57.K3(RX2VDD) ; also on sheet 30
1V0_XG_RX: C583.1 C584.1 C585.1 C587.1 C588.1 C589.1 C902.1 FB43.2 U57.C11(RX1VDD) U57.G5(RX1VDD) U57.G9(RX1VDD) U57.H7(RX1VDD) U57.J10(RX1VDD) U57.K9(RX1VDD)
1V0_XG_TX: C580.1 C581.1 C582.1 C901.1 FB42.2 U57.E8(TX1VDD) U57.E9(TX1VDD) U57.J7(TX1VDD)
1V0A_QSG1: C401.1 C402.1 C403.1 C404.1 C406.1 C407.1 C1082.1 FB35.2 U55.E1(VDD1A) U55.E11(VDD1A) U55.E14(VDD1A) U55.E16(VDD1A) U55.E28(VDD1A) U55.E30(VDD1A) U55.E32(VDD1A) U55.E34(VDD1A) U55.E36(VDD1A)
1V0A_QSG2: C446.1 C447.1 C448.1 C449.1 C450.1 C451.1 C1085.1 FB37.2 U56.E1(VDD1A) U56.E11(VDD1A) U56.E14(VDD1A) U56.E16(VDD1A) U56.E28(VDD1A) U56.E30(VDD1A) U56.E32(VDD1A) U56.E34(VDD1A) U56.E36(VDD1A)
1V5: C609.1 C610.1 C611.1 C612.1 C613.1 C614.1 J19.6(1.5V) J19.28(1.5V) J19.48(1.5V) J20.6(1.5V) J20.28(1.5V) J20.48(1.5V) ; also on sheet 30
1V8: C566.1 C567.1 C568.1 C569.1 C570.1 C571.1 C586.1 C1018.1 C1019.1 C1092.1 C1093.1 C1094.1 FB40.1 FB41.1 R380.2 R381.2 R382.1 R385.1 R387.2 R388.1 R389.2 U57.C4(BV1P8RX) U57.C5(BV1P8RX) U57.D7(V2P5) U57.G2(V2P5) U57.H11(V2P5) U57.J4(BV1P8) U57.J5(BV1P8) U58.8(VCC) ; also on sheet 8 12 31
1V8_XG_AV: C576.1 C577.1 C899.1 FB40.2 U57.J8(AV1P8) U57.J9(AV1P8)
1V8_XG_RX: C578.1 C579.1 C900.1 FB41.2 U57.C8(AV1P8RX) U57.C9(AV1P8RX)
2V5: C432.1 C433.1 C434.1 C435.1 C436.1 C437.1 C477.1 C478.1 C479.1 C480.1 C481.1 C482.1 C549.1 C1084.1 C1087.1 FB36.2 FB38.2 FB39.1 R293.2 R294.2 R295.2 R296.1 R314.2 R315.2 R316.2 R317.1 R855.2 R856.2 U55.E3(VDD25) U55.E4(VDD25) U55.E6(VDD25) U55.E8(VDD25) U55.E9(VDDMDIO) U55.E12(VDD25) U55.E18(VDD25) U55.E20(VDD25) U55.E22(VDD25) U55.E24(VDD25) U55.E26(VDD25) U56.E3(VDD25) U56.E4(VDD25) U56.E6(VDD25) U56.E8(VDD25) U56.E9(VDDMDIO) U56.E12(VDD25) U56.E18(VDD25) U56.E20(VDD25) U56.E22(VDD25) U56.E24(VDD25) U56.E26(VDD25) ; also on sheet 8 12 16 17 31
2V5_LED: C551.1 C552.1 FB39.2 J15.A9 J15.A11 J15.B9 J15.B11 J15.C9 J15.C11 J15.D9 J15.D11 J15.E9 J15.E11 J15.F9 J15.F11 J15.G9 J15.G11 J15.H9(G9) J15.H11(G11)
2V5A_QSG1: C412.1 C413.1 C414.1 C415.1 C416.1 FB36.1 U55.E27(VDD25A) U55.E29(VDD25A) U55.E31(VDD25A) U55.E33(VDD25A) U55.E35(VDD25A) U55.E37(VDD25A)
2V5A_QSG2: C457.1 C458.1 C459.1 C461.1 C462.1 FB38.1 U56.E27(VDD25A) U56.E29(VDD25A) U56.E31(VDD25A) U56.E33(VDD25A) U56.E35(VDD25A) U56.E37(VDD25A)
3V3: C590.1 C591.1 C594.1 C595.1 C600.1 C601.1 C602.1 C603.1 C604.1 C605.1 C626.1 C627.1 C628.1 C629.1 C652.1 C653.1 C654.1 C655.1 C656.1 C657.1 D36.2 D37.2 D38.2 D39.2 FB44.1 FB45.1 J18.A9(+3V3) J18.A10(+3V3) J18.B8(+3V3) J18.B10(+3V3AUX) J19.2(3.3V) J19.24(3.3VAUX) J19.52(3.3V) J20.2(3.3V) J20.24(3.3VAUX) J20.52(3.3V) R390.2 R391.2 R392.2 R393.2 R396.2 R397.2 R398.2 R399.2 R402.2 R403.2 R404.2 R405.2 R406.2 R407.2 R408.2 R409.2 R410.2 R411.2 R420.2 R428.2 R845.1 R847.1 R857.2 U59.7(AVDD) U59.25(DVDD) U59.37(DVDD) U59.54(AVDD) U59.57(AVDD) ; also on sheet 3 5 6 7 9 10 12 14 16 17 24 28 29 31 32
3V3_SFPP_VDDR: C592.1 C593.1 FB44.2 J16.15(VDDR)
3V3_SFPP_VDDT: C596.1 C597.1 FB45.2 J16.16(VDDT)
12V: C620.1 C621.1 C622.1 C623.1 C624.1 C625.1 J18.A2(+12V) J18.A3(+12V) J18.B1(+12V) J18.B2(+12V) J18.B3(+12V) ; also on sheet 10 25 31 32
GND: C401.2 C402.2 C403.2 C404.2 C406.2 C407.2 C412.2 C413.2 C414.2 C415.2 C416.2 C420.2 C421.2 C422.2 C423.2 C424.2 C425.2 C432.2 C433.2 C434.2 C435.2 C436.2 C437.2 C440.2 C446.2 C447.2 C448.2 C449.2 C450.2 C451.2 C457.2 C458.2 C459.2 C461.2 C462.2 C465.2 C466.2 C467.2 C468.2 C469.2 C470.2 C477.2 C478.2 C479.2 C480.2 C481.2 C482.2 C485.2 C490.1 C491.1 C492.1 C493.1 C494.1 C495.1 C496.1 C497.1 C500.1 C501.1 C502.1 C503.1 C504.1 C505.1 C506.1 C507.1 C508.1 C509.1 C510.1 C511.1 C514.1 C515.1 C516.1 C517.1 C518.1 C519.1 C520.1 C521.1 C522.1 C523.1 C524.1 C525.1 C528.1 C529.1 C530.1 C531.1 C532.1 C533.1 C534.1 C535.1 C536.1 C537.1 C538.1 C539.1 C540.1 C543.1 C544.1 C545.1 C546.1 C547.1 C548.1 C549.2 C550.1 C551.2 C552.2 C553.1 C556.2 C557.2 C558.2 C559.2 C560.2 C561.2 C562.2 C563.2 C564.1 C565.1 C566.2 C567.2 C568.2 C569.2 C570.2 C571.2 C572.2 C573.2 C576.2 C577.2 C578.2 C579.2 C580.2 C581.2 C582.2 C583.2 C584.2 C585.2 C586.2 C587.2 C588.2 C589.2 C590.2 C591.2 C592.2 C593.2 C594.2 C595.2 C596.2 C597.2 C600.2 C601.2 C602.2 C603.2 C604.2 C605.2 C609.2 C610.2 C611.2 C612.2 C613.2 C614.2 C620.2 C621.2 C622.2 C623.2 C624.2 C625.2 C626.2 C627.2 C628.2 C629.2 C636.2 C639.2 C640.1 C641.2 C643.1 C645.2 C646.1 C649.2 C650.2 C651.2 C652.2 C653.2 C654.2 C655.2 C656.2 C657.2 C899.2 C900.2 C901.2 C902.2 C903.2 C1018.2 C1019.2 C1020.2 C1021.2 C1082.2 C1083.2 C1084.2 C1085.2 C1086.2 C1087.2 C1088.2 C1089.2 C1090.2 C1091.2 C1092.2 C1093.2 C1094.2 J16.1(TGND) J16.10(RGND) J16.11(RGND) J16.14(RGND) J16.17(TGND) J16.20(TGND) J18.A1(~{PRSNT1}) J18.A4(GND) J18.A12(GND) J18.A15(GND) J18.A18(GND) J18.A20(GND) J18.A23(GND) J18.A24(GND) J18.A27(GND) J18.A28(GND) J18.A31(GND) J18.B4(GND) J18.B7(GND) J18.B13(GND) J18.B16(GND) J18.B18(GND) J18.B21(GND) J18.B22(GND) J18.B25(GND) J18.B26(GND) J18.B29(GND) J18.B32(GND) J19.4(GND) J19.9(GND) J19.15(GND) J19.18(GND) J19.21(GND) J19.26(GND) J19.27(GND) J19.29(GND) J19.34(GND) J19.35(GND) J19.40(GND) J19.50(GND) J19.53(MS1) J19.54(MS2) J20.4(GND) J20.9(GND) J20.15(GND) J20.18(GND) J20.21(GND) J20.26(GND) J20.27(GND) J20.29(GND) J20.34(GND) J20.35(GND) J20.40(GND) J20.50(GND) J20.53(MS1) J20.54(MS2) J21.1(GND) J21.4(GND) J21.7(GND) J21.8(MH1) J21.9(MH2) M3.1 M4.1 M5.1 M6.1 M7.1 M8.1 M9.1 M10.1 M11.1 M12.1 M13.1 M14.1 M15.1 M16.1 M17.1 M18.1 R297.1 R302.1 R303.1 R320.1 R323.1 R324.1 R379.2 R383.2 R384.2 R400.2 R401.2 R438.1 R846.2 R848.2 U55.139(VSS_CASE) U55.B7(REFCLK_SEL1) U55.B8(REFCLK_SEL0) U55.D9(VSS/EFUSE) U56.139(VSS_CASE) U56.B7(REFCLK_SEL1) U56.B8(REFCLK_SEL0) U56.D9(VSS/EFUSE) U57.A3(DIGVSS) U57.A6(DIGVSS) U57.A9(DIGVSS) U57.B1(TX2VSS) U57.B2(TX2VSS) U57.B3(RX2VSS) U57.B4(RX2VSS) U57.B5(RX2VSS) U57.B7(TX1VSS) U57.B8(TX1VSS) U57.B9(RX1VSS) U57.B10(RX1VSS) U57.B11(RX1VSS) U57.D2(TX2VSS) U57.D4(RX2VSS) U57.D5(RX2VSS) U57.D8(RX1VSS) U57.D9(RX1VSS) U57.E1(TX2VSS) U57.E6(DIGVSS) U57.E7(DIGVSS) U57.F4(RX2VSS) U57.F5(RX2VSS) U57.F8(RX1VSS) U57.F9(RX1VSS) U57.G6(RX2VSS) U57.G7(TX1VSS) U57.H4(TX2VSS) U57.H5(TX2VSS) U57.H8(TX1VSS) U57.H9(RX1VSS) U57.K1(TX2VSS) U57.K2(TX2VSS) U57.K4(RX2VSS) U57.K5(RX2VSS) U57.K6(TX1VSS) U57.K7(TX1VSS) U57.K8(TX1VSS) U57.K10(RX1VSS) U57.K11(RX1VSS) U57.L3(RX2VSS) U57.L6(TX1VSS) U57.L9(RX1VSS) U58.1(A0) U58.2(A1) U58.3(A2) U58.4(GND) U58.7(WP) U59.5(BGND1) U59.8(AGND) U59.23(DGND) U59.39(DGND) U59.43(SWISZ) U59.53(AGND) U59.56(AGND) U59.58(BGND2) U59.81(EPAD) U60.6 U60.7 U61.6 U61.7 ; also on sheet 3 4 5 6 7 8 9 10 11 12 13 14 15 16 17 24 25 26 27 28 29 30 31 32 33
VBATH: C636.1 C645.1 C651.1 R430.1 U59.1(VBM1) U59.3(VBH) U59.60(VBM2) U60.2 U61.2 ; also on sheet 24 25
VBATL: C650.1 R433.1 U59.69(VBL2) U59.79(VBL1) ; also on sheet 24 25
EARTH: C498.1 C499.1 C512.1 C513.1 C526.1 C527.1 C541.1 C542.1 C544.2 C545.2 C548.2 C550.2 C553.2 J15.97 J15.98 J15.99 J15.100 J17.1(MH1) J17.2(MH2) J17.3(MH3) J17.4(MH4) J17.5(MH5) J17.6(MH6) J17.7(MH7) J17.8(MH8) J17.9(MH9) J17.10(MH10) J17.11(MH11) J17.12(MH12) J17.13(MH13) J17.14(MH14) J17.15(MH15) J17.16(MH16) J17.17(MH17) J17.18(MH18) J17.20(MH20) ; also on sheet 11 14 15 16 17 33
EMI1_MDC: U55.C11(MDC) U56.C11(MDC) ; also on sheet 8 16 17
EMI1_MDIO: U55.D10(MDIO) U56.D10(MDIO) ; also on sheet 8 16 17
EMI2_MDC: U57.G1(MDC) ; also on sheet 8
EMI2_MDIO: U57.F1(MDIO) ; also on sheet 8
FXS1_LED: R439.1 ; also on sheet 26
FXS2_LED: R440.1 ; also on sheet 26
I2C2_MPEX1_SCL: J19.30(SMB_CLK) R398.1 ; also on sheet 7
I2C2_MPEX1_SDA: J19.32(SMB_DATA) R404.1 ; also on sheet 7
I2C2_MPEX2_SCL: J20.30(SMB_CLK) R409.1 ; also on sheet 7
I2C2_MPEX2_SDA: J20.32(SMB_DATA) R410.1 ; also on sheet 7
I2C2_PEX_SCL: J18.B5(SMCLK) R406.1 ; also on sheet 7
I2C2_PEX_SDA: J18.B6(SMDAT) R407.1 ; also on sheet 7
I2C2_SFPP_SCL: J16.5(MOD_DEF(1)/SCL) R392.1 ; also on sheet 7
I2C2_SFPP_SDA: J16.4(MOD_DEF(2)/SDA) R391.1 ; also on sheet 7
MPEX1_REFCLK_N: J19.13(REFCLK+) ; also on sheet 27
MPEX1_REFCLK_P: J19.11(REFCLK-) ; also on sheet 27
MPEX1_RST_N: J19.22(~{PERST}) ; also on sheet 26
MPEX1_RX_N: J19.23(PERN0) ; also on sheet 9
MPEX1_RX_P: J19.25(PERP0) ; also on sheet 9
MPEX1_TX_N: C599.2 ; also on sheet 9
MPEX1_TX_P: C598.2 ; also on sheet 9
MPEX2_REFCLK_N: J20.13(REFCLK+) ; also on sheet 27
MPEX2_REFCLK_P: J20.11(REFCLK-) ; also on sheet 27
MPEX2_RST_N: J20.22(~{PERST}) ; also on sheet 26
MPEX2_RX_N: J20.23(PERN0) ; also on sheet 9
MPEX2_RX_P: J20.25(PERP0) ; also on sheet 9
MPEX2_TX_N: C631.2 ; also on sheet 9
MPEX2_TX_P: C630.2 ; also on sheet 9
PEX_PRS_N: J18.B17(~{PRSNT2}_X1) J18.B31(~{PRSNT2}_X4) R405.1 ; also on sheet 26
PEX_REFCLK_N: J18.A14(REFCLK-) ; also on sheet 27
PEX_REFCLK_P: J18.A13(REFCLK+) ; also on sheet 27
PEX_RST_N: J18.A11(~{PERST}) ; also on sheet 26
PEX_RX0_N: J18.A17(PERN0) ; also on sheet 8
PEX_RX0_P: J18.A16(PERP0) ; also on sheet 8
PEX_RX1_N: J18.A22(PERN1) ; also on sheet 9
PEX_RX1_P: J18.A21(PERP1) ; also on sheet 9
PEX_RX2_N: J18.A26(PERN2) ; also on sheet 9
PEX_RX2_P: J18.A25(PERP2) ; also on sheet 9
PEX_RX3_N: J18.A30(PERN3) ; also on sheet 9
PEX_RX3_P: J18.A29(PERP3) ; also on sheet 9
PEX_TX0_N: C607.2 ; also on sheet 8
PEX_TX0_P: C606.2 ; also on sheet 8
PEX_TX1_N: C615.2 ; also on sheet 9
PEX_TX1_P: C608.2 ; also on sheet 9
PEX_TX2_N: C617.2 ; also on sheet 9
PEX_TX2_P: C616.2 ; also on sheet 9
PEX_TX3_N: C619.2 ; also on sheet 9
PEX_TX3_P: C618.2 ; also on sheet 9
POTS1_RING: F2.2 J22.A3 R413.2
POTS1_TIP: F1.2 J22.A4 R412.2
POTS2_RING: F4.2 J22.B3 R435.2
POTS2_TIP: F3.2 J22.B4 R434.2
POTS_RST_N: R426.1 R857.1 ; also on sheet 24
POTS_SWCMP: U59.20(SWCMPY) ; also on sheet 25
POTS_SWIS: U59.19(SWISY) ; also on sheet 25
POTS_SWOUT: U59.21(SWOUTY) ; also on sheet 25
POTS_TDM_CLK: R417.1 ; also on sheet 7 24
POTS_TDM_FS: R418.1 ; also on sheet 7 24
POTS_TDM_RXD: R422.1 ; also on sheet 7 24
POTS_TDM_TXD: R421.1 ; also on sheet 7 24
POTSA_INT_N: R428.1 U59.31(~{INT}/S2) ; also on sheet 26
POTSA_SPI_CS_N: R420.1 U59.36(~{CS}/PG) ; also on sheet 6
POTSA_SWVSY: U59.18(SWVSY) ; also on sheet 25
POTSA_SWVSZ: U59.44(SWVSZ) ; also on sheet 25
QSG1_INT_N: R291.2 R855.1 ; also on sheet 26
QSG1_LED0: R340.1 U55.C3(LED0_PHY1)
QSG1_LED1: R342.1 U55.B2(LED1_PHY1)
QSG1_MDI0_N: T5.3 U55.B17(P1_D0N)
QSG1_MDI0_P: T5.2 U55.B18(P1_D0P)
QSG1_MDI1_N: T5.6 U55.C28(P1_D1N)
QSG1_MDI1_P: T5.5 U55.C29(P1_D1P)
QSG1_MDI2_N: T5.9 U55.B15(P1_D2N)
QSG1_MDI2_P: T5.8 U55.B16(P1_D2P)
QSG1_MDI3_N: T5.12 U55.C26(P1_D3N)
QSG1_MDI3_P: T5.11 U55.C27(P1_D3P)
QSG1_MDX0_N: J15.A2 T5.22
QSG1_MDX0_P: J15.A1 T5.23
QSG1_MDX1_N: J15.A6 T5.19
QSG1_MDX1_P: J15.A3 T5.20
QSG1_MDX2_N: J15.A5 T5.16
QSG1_MDX2_P: J15.A4 T5.17
QSG1_MDX3_N: J15.A8 T5.13
QSG1_MDX3_P: J15.A7 T5.14
QSG1_REFCLK_N: C411.1 ; also on sheet 28
QSG1_REFCLK_P: C410.1 ; also on sheet 28
QSG1_RST_N: R292.1 R296.2 ; also on sheet 26
QSG2_INT_N: R312.2 R856.1 ; also on sheet 26
QSG2_LED0: R352.1 U55.E2(LED0_PHY0)
QSG2_LED1: R354.1 U55.D1(LED1_PHY0)
QSG2_MDI0_N: T7.3 U55.D30(P0_D0N)
QSG2_MDI0_P: T7.2 U55.D31(P0_D0P)
QSG2_MDI1_N: T7.6 U55.C24(P0_D1N)
QSG2_MDI1_P: T7.5 U55.C25(P0_D1P)
QSG2_MDI2_N: T7.9 U55.C23(P0_D2N)
QSG2_MDI2_P: T7.8 U55.D29(P0_D2P)
QSG2_MDI3_N: T7.12 U55.C21(P0_D3N)
QSG2_MDI3_P: T7.11 U55.C22(P0_D3P)
QSG2_MDX0_N: J15.B2 T7.22
QSG2_MDX0_P: J15.B1 T7.23
QSG2_MDX1_N: J15.B6 T7.19
QSG2_MDX1_P: J15.B3 T7.20
QSG2_MDX2_N: J15.B5 T7.16
QSG2_MDX2_P: J15.B4 T7.17
QSG2_MDX3_N: J15.B8 T7.13
QSG2_MDX3_P: J15.B7 T7.14
QSG2_REFCLK_N: C456.1 ; also on sheet 28
QSG2_REFCLK_P: C455.1 ; also on sheet 28
QSG2_RST_N: R313.1 R317.2 ; also on sheet 26
QSG3_LED0: R364.1 U55.B4(LED0_PHY3)
QSG3_LED1: R366.1 U55.C6(LED1_PHY3)
QSG3_MDI0_N: T9.3 U55.C36(P3_D0N)
QSG3_MDI0_P: T9.2 U55.C1(P3_D0P)
QSG3_MDI1_N: T9.6 U55.D34(P3_D1N)
QSG3_MDI1_P: T9.5 U55.D35(P3_D1P)
QSG3_MDI2_N: T9.9 U55.C34(P3_D2N)
QSG3_MDI2_P: T9.8 U55.C35(P3_D2P)
QSG3_MDI3_N: T9.12 U55.D32(P3_D3N)
QSG3_MDI3_P: T9.11 U55.D33(P3_D3P)
QSG3_MDX0_N: J15.C2 T9.22
QSG3_MDX0_P: J15.C1 T9.23
QSG3_MDX1_N: J15.C6 T9.19
QSG3_MDX1_P: J15.C3 T9.20
QSG3_MDX2_N: J15.C5 T9.16
QSG3_MDX2_P: J15.C4 T9.17
QSG3_MDX3_N: J15.C8 T9.13
QSG3_MDX3_P: J15.C7 T9.14
QSG4_LED0: R375.1 U55.C5(LED0_PHY2)
QSG4_LED1: R376.1 U55.D5(LED1_PHY2)
QSG4_MDI0_N: T11.3 U55.C32(P2_D0N)
QSG4_MDI0_P: T11.2 U55.C33(P2_D0P)
QSG4_MDI1_N: T11.6 U55.B19(P2_D1N)
QSG4_MDI1_P: T11.5 U55.B20(P2_D1P)
QSG4_MDI2_N: T11.9 U55.A9(P2_D2N)
QSG4_MDI2_P: T11.8 U55.A10(P2_D2P)
QSG4_MDI3_N: T11.12 U55.C30(P2_D3N)
QSG4_MDI3_P: T11.11 U55.C31(P2_D3P)
QSG4_MDX0_N: J15.D2 T11.22
QSG4_MDX0_P: J15.D1 T11.23
QSG4_MDX1_N: J15.D6 T11.19
QSG4_MDX1_P: J15.D3 T11.20
QSG4_MDX2_N: J15.D5 T11.16
QSG4_MDX2_P: J15.D4 T11.17
QSG4_MDX3_N: J15.D8 T11.13
QSG4_MDX3_P: J15.D7 T11.14
QSG5_LED0: R339.1 U56.C3(LED0_PHY1)
QSG5_LED1: R341.1 U56.B2(LED1_PHY1)
QSG5_MDI0_N: T4.3 U56.B17(P1_D0N)
QSG5_MDI0_P: T4.2 U56.B18(P1_D0P)
QSG5_MDI1_N: T4.6 U56.C28(P1_D1N)
QSG5_MDI1_P: T4.5 U56.C29(P1_D1P)
QSG5_MDI2_N: T4.9 U56.B15(P1_D2N)
QSG5_MDI2_P: T4.8 U56.B16(P1_D2P)
QSG5_MDI3_N: T4.12 U56.C26(P1_D3N)
QSG5_MDI3_P: T4.11 U56.C27(P1_D3P)
QSG5_MDX0_N: J15.E2 T4.22
QSG5_MDX0_P: J15.E1 T4.23
QSG5_MDX1_N: J15.E6 T4.19
QSG5_MDX1_P: J15.E3 T4.20
QSG5_MDX2_N: J15.E5 T4.16
QSG5_MDX2_P: J15.E4 T4.17
QSG5_MDX3_N: J15.E8 T4.13
QSG5_MDX3_P: J15.E7 T4.14
QSG6_LED0: R351.1 U56.E2(LED0_PHY0)
QSG6_LED1: R353.1 U56.D1(LED1_PHY0)
QSG6_MDI0_N: T6.3 U56.D30(P0_D0N)
QSG6_MDI0_P: T6.2 U56.D31(P0_D0P)
QSG6_MDI1_N: T6.6 U56.C24(P0_D1N)
QSG6_MDI1_P: T6.5 U56.C25(P0_D1P)
QSG6_MDI2_N: T6.9 U56.C23(P0_D2N)
QSG6_MDI2_P: T6.8 U56.D29(P0_D2P)
QSG6_MDI3_N: T6.12 U56.C21(P0_D3N)
QSG6_MDI3_P: T6.11 U56.C22(P0_D3P)
QSG6_MDX0_N: J15.F2 T6.22
QSG6_MDX0_P: J15.F1 T6.23
QSG6_MDX1_N: J15.F6 T6.19
QSG6_MDX1_P: J15.F3 T6.20
QSG6_MDX2_N: J15.F5 T6.16
QSG6_MDX2_P: J15.F4 T6.17
QSG6_MDX3_N: J15.F8 T6.13
QSG6_MDX3_P: J15.F7 T6.14
QSG7_LED0: R363.1 U56.B4(LED0_PHY3)
QSG7_LED1: R365.1 U56.C6(LED1_PHY3)
QSG7_MDI0_N: T8.3 U56.C36(P3_D0N)
QSG7_MDI0_P: T8.2 U56.C1(P3_D0P)
QSG7_MDI1_N: T8.6 U56.D34(P3_D1N)
QSG7_MDI1_P: T8.5 U56.D35(P3_D1P)
QSG7_MDI2_N: T8.9 U56.C34(P3_D2N)
QSG7_MDI2_P: T8.8 U56.C35(P3_D2P)
QSG7_MDI3_N: T8.12 U56.D32(P3_D3N)
QSG7_MDI3_P: T8.11 U56.D33(P3_D3P)
QSG7_MDX0_N: J15.G2 T8.22
QSG7_MDX0_P: J15.G1 T8.23
QSG7_MDX1_N: J15.G6 T8.19
QSG7_MDX1_P: J15.G3 T8.20
QSG7_MDX2_N: J15.G5 T8.16
QSG7_MDX2_P: J15.G4 T8.17
QSG7_MDX3_N: J15.G8 T8.13
QSG7_MDX3_P: J15.G7 T8.14
QSG8_LED0: R377.1 U56.C5(LED0_PHY2)
QSG8_LED1: R378.1 U56.D5(LED1_PHY2)
QSG8_MDI0_N: T10.3 U56.C32(P2_D0N)
QSG8_MDI0_P: T10.2 U56.C33(P2_D0P)
QSG8_MDI1_N: T10.6 U56.B19(P2_D1N)
QSG8_MDI1_P: T10.5 U56.B20(P2_D1P)
QSG8_MDI2_N: T10.9 U56.A9(P2_D2N)
QSG8_MDI2_P: T10.8 U56.A10(P2_D2P)
QSG8_MDI3_N: T10.12 U56.C30(P2_D3N)
QSG8_MDI3_P: T10.11 U56.C31(P2_D3P)
QSG8_MDX0_N: J15.H2(G2) T10.22
QSG8_MDX0_P: J15.H1(G1) T10.23
QSG8_MDX1_N: J15.H6(G6) T10.19
QSG8_MDX1_P: J15.H3(G3) T10.20
QSG8_MDX2_N: J15.H5(G5) T10.16
QSG8_MDX2_P: J15.H4(G4) T10.17
QSG8_MDX3_N: J15.H8(G8) T10.13
QSG8_MDX3_P: J15.H7(G7) T10.14
QSGMII1_RX_N: U55.D13(QSGMII0_RXN) ; also on sheet 9
QSGMII1_RX_P: U55.D14(QSGMII0_RXP) ; also on sheet 9
QSGMII1_TX_N: C405.1 ; also on sheet 9
QSGMII1_TX_P: C400.1 ; also on sheet 9
QSGMII2_RX_N: U56.D13(QSGMII0_RXN) ; also on sheet 8
QSGMII2_RX_P: U56.D14(QSGMII0_RXP) ; also on sheet 8
QSGMII2_TX_N: C454.1 ; also on sheet 8
QSGMII2_TX_P: C445.1 ; also on sheet 8
SATA_RX_N: C634.1 ; also on sheet 9
SATA_RX_P: C635.1 ; also on sheet 9
SATA_TX_N: C633.1 ; also on sheet 9
SATA_TX_P: C632.1 ; also on sheet 9
SFPP_DET_N: J16.6(MOD_DEF(0)/DET) R393.1 ; also on sheet 26
SFPP_RX_N: J16.12(RX_DAT-) U57.L11(RX1_DINN)
SFPP_RX_P: J16.13(RX_DAT+) U57.L10(RX1_DINP)
SFPP_RXLOS: J16.8(RX_LOS) R390.1 ; also on sheet 26
SFPP_TX_N: J16.19(TX_DAT-) U57.L7(TX1_DOUTN)
SFPP_TX_P: J16.18(TX_DAT+) U57.L8(TX1_DOUTP)
SFPP_TXDIS: J16.3(TX_DIS) R396.1 ; also on sheet 26
SFPP_TXFAIL: J16.2(TX_FAULT) R397.1 ; also on sheet 26
SPI_CLK: R425.1 ; also on sheet 6 10 24
SPI_MISO: R419.1 ; also on sheet 6 10 24
SPI_MOSI: R423.1 ; also on sheet 6 10 24
XFI_RX_N: U57.A11(XRX1_DOUTN) ; also on sheet 8
XFI_RX_P: U57.A10(XRX1_DOUTP) ; also on sheet 8
XFI_TX_N: C555.1 ; also on sheet 8
XFI_TX_P: C554.1 ; also on sheet 8
XG_LED0: R394.1 ; also on sheet 26
XG_LED1: R395.1 ; also on sheet 26
XG_REFCLK_N: C575.1 ; also on sheet 28
XG_REFCLK_P: C574.1 ; also on sheet 28
XG_RST_N: R386.1 R388.2 ; also on sheet 26
N16848026: R422.2 U59.28(DXA/DU)
N16848521: R423.2 U59.34(DIN/S1)
N16848537: R426.2 U59.32(~{RST})
N16848601: R419.2 U59.35(DOUT)
N16849665: R436.2 U59.9(RTV1)
N16849667: R436.1 U59.6(RSN1)
N16849681: C648.2 U59.51(IHL2)
N16849691: C646.2 C647.1 C648.1 U59.17(VREF)
N16849695: C647.2 U59.10(IHL1)
N16849815: R437.1 U59.52(RTV2)
N16849817: R437.2 U59.55(RSN2)
N16849836: R438.2 U59.16(IREF)
N16849860: C649.1 U59.15(LFC1)
N16850380: C639.1 F1.1 R414.2 U59.77(TIPD1) U60.1 U60.8
N16850382: C640.2 F2.1 R416.2 U59.71(RINGD1) U60.4 U60.5
N16850384: R716.1 U59.13(TDC1)
N16850386: R717.1 U59.14(RDC1)
N16850446: C637.2 R414.1
N16850448: C637.1 U59.11(TAC1)
N16850461: C638.1 U59.12(RAC1)
N16850463: C638.2 R416.1
N16850577: C641.1 F3.1 R429.2 U59.67(TIPD2) U61.1 U61.8
N16850645: C643.2 F4.1 R431.2 U59.61(RINGD2) U61.4 U61.5
N16850749: C642.1 U59.50(TAC2)
N16850755: C644.1 U59.49(RAC2)
N16850778: R718.1 U59.47(RDC2)
N16850798: R719.1 U59.48(TDC2)
N16859448: R430.2 R433.2 U59.45(XB)
N16861709: R421.2 U59.29(DRA/DD)
N16861730: R418.2 U59.26(FS/FSC)
N16930193: C555.2 U57.A8(XTX1_DINN)
N16930196: C554.2 U57.A7(XTX1_DINP)
N16936676: C574.2 U57.C1(REFCLKP)
N16936678: C575.2 U57.D1(REFCLKN)
N16941914: R379.1 U57.F2(MADDR1)
N16941931: R380.1 U57.E2(MADDR2)
N16941947: R381.1 U57.H2(MADDR3)
N16941963: R383.1 U57.F3(MADDR4)
N16943000: R384.1 U57.B6(MICROSEL)
N16943224: R387.1 U57.E10(MDIOSEL)
N16943474: R382.2 U57.H3(SCL) U58.6(SCL)
N16943477: R385.2 U57.G3(SDA) U58.5(SDA)
N16948831: R386.2 U57.H10(~{RESET})
N16948977: R389.1 U57.J6(IO_VDD_SEL)
N16949711: C572.1 U57.L4(RX2_DINP)
N16949714: C573.1 U57.L5(RX2_DINN)
N16950393: C564.2 U57.A1(XTX2_DINP)
N16950396: C565.2 U57.A2(XTX2_DINN)
N16956674: J16.7(RS0) R845.2 R846.1
N16956686: J16.9(RS1) R847.2 R848.1
N16980127: J18.B11(~{WAKE}) R408.1
N16980167: J18.A8(JTAG5_TMS) R403.1
N16980179: J18.B9(JTAG1_~{TRST}) R400.1
N16980191: J18.A5(JTAG2_TCK) R401.1
N16980203: J18.A6(JTAG3_TDI) R402.1
N16980532: C607.1 J18.B15(PETN0)
N16980534: C606.1 J18.B14(PETP0)
N16981083: C608.1 J18.B19(PETP1)
N16981085: C615.1 J18.B20(PETN1)
N16981142: C616.1 J18.B23(PETP2)
N16981144: C617.1 J18.B24(PETN2)
N16981213: C618.1 J18.B27(PETP3)
N16981215: C619.1 J18.B28(PETN3)
N16984231: C598.1 J19.33(PETP0)
N16984233: C599.1 J19.31(PETN0)
N16985354: C630.1 J20.33(PETP0)
N16985356: C631.1 J20.31(PETN0)
N17111815: J19.1(~{WAKE}) R399.1
N17112169: J20.1(~{WAKE}) R411.1
N17447445: C642.2 R429.1
N17447447: C644.2 R431.1
N17540556: R417.2 U59.30(PCLK/DCL)
N17540577: R425.2 U59.33(DCLK/S0)
N17582904: R332.1 T5.24
N17582906: C499.2 R332.2 R334.2 R336.2 R338.2
N17582916: R334.1 T5.21
N17582920: R336.1 T5.18
N17582932: R338.1 T5.15
N17584869: R291.1 U55.C10(MDINT)
N17602850: C490.2 T5.1
N17602860: C493.2 T5.4
N17602866: C495.2 T5.7
N17602896: C497.2 T5.10
N17604579: R302.2 U55.C7(~{JTAG_TRST})
N17629033: R294.1 U55.B12(PHYADD3)
N17629034: R295.1 U55.D26(PHYADD4)
N17629035: R293.1 U55.C19(PHYADD2)
N17629369: R292.2 U55.B5(~{RESET})
N17629454: R297.2 U55.D8(COMA_MODE)
N17629729: C440.1 U55.A7(REF_FILT)
N17629871: R303.2 U55.A8(REF_REXT)
N17632317: R344.1 T7.24
N17632319: C513.2 R344.2 R346.2 R348.2 R350.2
N17632321: R346.1 T7.21
N17632325: R348.1 T7.18
N17632337: R350.1 T7.15
N17632390: C505.2 T7.1
N17632398: C507.2 T7.4
N17632406: C509.2 T7.7
N17632436: C511.2 T7.10
N17632726: C527.2 R356.2 R358.2 R360.2 R362.2
N17632728: R356.1 T9.24
N17632740: R360.1 T9.18
N17632744: R358.1 T9.21
N17632760: R362.1 T9.15
N17632797: C521.2 T9.4
N17632805: C519.2 T9.1
N17632821: C523.2 T9.7
N17632853: C525.2 T9.10
N17633242: R368.1 T11.24
N17633244: C542.2 R368.2 R370.2 R372.2 R374.2
N17633254: R370.1 T11.21
N17633258: R372.1 T11.18
N17633270: R374.1 T11.15
N17633303: C535.2 T11.4
N17633315: C533.2 T11.1
N17633335: C537.2 T11.7
N17633357: C539.2 T11.10
N17639917: C485.1 U56.A7(REF_FILT)
N17639934: R324.2 U56.A8(REF_REXT)
N17639958: R725.2 U56.D18(SEDES_REXT_1)
N17639964: R725.1 U56.D17(SEDES_REXT_0)
N17639984: R323.2 U56.C7(~{JTAG_TRST})
N17640717: R312.1 U56.C10(MDINT)
N17640929: R315.1 U56.B12(PHYADD3)
N17640931: R316.1 U56.D26(PHYADD4)
N17640933: R314.1 U56.C19(PHYADD2)
N17640965: R313.2 U56.B5(~{RESET})
N17640979: R320.2 U56.D8(COMA_MODE)
N17775417: C501.2 J15.A12 R342.2
N17775429: C503.2 J15.A10 R340.2
N17779755: C515.2 J15.B12 R354.2
N17779761: C517.2 J15.B10 R352.2
N17780053: C529.2 J15.C12 R366.2
N17780059: C531.2 J15.C10 R364.2
N17780366: C540.2 J15.D12 R376.2
N17780372: C543.2 J15.D10 R375.2
N17787749: C546.2 J15.H12(G12) R378.2
N17787773: C547.2 J15.H10(G10) R377.2
N17787818: C498.2 R331.2 R333.2 R335.2 R337.2
N17787822: C512.2 R343.2 R345.2 R347.2 R349.2
N17787848: C526.2 R355.2 R357.2 R359.2 R361.2
N17787852: C541.2 R367.2 R369.2 R371.2 R373.2
N17787943: R331.1 T4.24
N17787947: R333.1 T4.21
N17787951: R335.1 T4.18
N17787955: R337.1 T4.15
N17787993: C491.2 T4.1
N17788013: C492.2 T4.4
N17788019: C494.2 T4.7
N17788035: C496.2 T4.10
N17788175: R343.1 T6.24
N17788179: R345.1 T6.21
N17788183: R347.1 T6.18
N17788187: R349.1 T6.15
N17788233: C504.2 T6.1
N17788241: C506.2 T6.4
N17788251: C508.2 T6.7
N17788275: C510.2 T6.10
N17788409: R357.1 T8.21
N17788413: R355.1 T8.24
N17788425: R361.1 T8.15
N17788429: R359.1 T8.18
N17788459: C520.2 T8.4
N17788477: C518.2 T8.1
N17788487: C522.2 T8.7
N17788519: C524.2 T8.10
N17788647: R367.1 T10.24
N17788651: R369.1 T10.21
N17788663: R371.1 T10.18
N17788667: R373.1 T10.15
N17788695: C534.2 T10.4
N17788701: C532.2 T10.1
N17788725: C536.2 T10.7
N17788759: C538.2 T10.10
N17788879: C500.2 J15.E12 R341.2
N17788889: C502.2 J15.E10 R339.2
N17788969: C514.2 J15.F12 R353.2
N17788975: C516.2 J15.F10 R351.2
N17789051: C528.2 J15.G12 R365.2
N17789057: C530.2 J15.G10 R363.2
N17823659: C411.2 U55.D12(REFCLK_N)
N17823662: C410.2 U55.D11(REFCLK_P)
N17824163: C456.2 U56.D12(REFCLK_N)
N17824166: C455.2 U56.D11(REFCLK_P)
N18629376: C405.2 U55.D15(QSGMII0_TXN)
N18629379: C400.2 U55.D16(QSGMII0_TXP)
N18629428: C454.2 U56.D15(QSGMII0_TXN)
N18629431: C445.2 U56.D16(QSGMII0_TXP)
N18629823: C633.2 J21.3(TX_N)
N18629826: C632.2 J21.2(TX_P)
N18629885: C634.2 J21.5(RX_N)
N18629888: C635.2 J21.6(RX_P)
N18636371: D38.1 R439.2
N18636375: D39.1 R440.2
N18648944: D36.1 R394.2
N18648948: D37.1 R395.2
N19535322: R412.1 R716.2
N19535325: R413.1 R717.2
N19535364: R435.1 R719.2
N19535367: R434.1 R718.2
N19675149: R724.2 U55.D18(SEDES_REXT_1)
N19675151: R724.1 U55.D17(SEDES_REXT_0)

Not connected (* = marked no-connect by the designer): J17 19(MH19)*; J18 A7(JTAG4_TDO)* A19(RSVD2)* A32(RSVD4)* B12(RSVD1)* B30(RSVD3)*; J19 3(RSVD1)* 5(RSVD2)* 7(~{CLKREQ})* 8(RSVD3)* 10(RSVD4)* 12(RSVD5)* 14(RSVD6)* 16(RSVD7)* 17(RSVD8)* 19(RSVD9)* 20(RSVD10)* 36(USB_D-)* 37(RSVD11)* 38(USB_D+)* 39(RSVD12)* 41(RSVD13)* 42(~{LED_WWAN})* 43(RSVD14)* 44(~{LED_WLAN})* 45(RSVD15)* 46(~{LED_WPAN})* 47(RSVD16)* 49(RSVD17)* 51(RSVD18)*; J20 3(RSVD1)* 5(RSVD2)* 7(~{CLKREQ})* 8(RSVD3)* 10(RSVD4)* 12(RSVD5)* 14(RSVD6)* 16(RSVD7)* 17(RSVD8)* 19(RSVD9)* 20(RSVD10)* 36(USB_D-)* 37(RSVD11)* 38(USB_D+)* 39(RSVD12)* 41(RSVD13)* 42(~{LED_WWAN})* 43(RSVD14)* 44(~{LED_WLAN})* 45(RSVD15)* 46(~{LED_WPAN})* 47(RSVD16)* 49(RSVD17)* 51(RSVD18)*; J22 A1* A2* A5* A6* B1* B2* B5* B6*; U55 A1(NC1)* A2(LED2_PHY3)* A3(JTAG_TMS)* A4(NC2)* A5(NC3)* A6(NC4)* B1(THERMDA)* B3(LED2_PHY2)* B6(JTAG_CLK)* B9(GPIO4)* B10(GPIO7)* B11(GPIO13)* B13(RCVRD_CLK0)* B14(TANA_1/NC)* C2(LED3_PHY0)* C4(LED2_PHY1)* C8(JTAG_DO)* C9(JTAG_DI)* C12(HSTST_P/NC)* C13(HSTST_N/NC)* C14(GPIO1)* C15(GPIO3)* C16(GPIO5)* C17(GPIO8)* C18(GPIO12)* C20(RCVRD_CLK1)* D2(LED2_PHY0)* D3(THERMDC_VSS)* D4(LED3_PHY1)* D6(LED3_PHY2)* D7(LED3_PHY3)* D19(GPIO0)* D20(GPIO2)* D21(GPIO6)* D22(GPIO9)* D23(GPIO11)* D24(GPIO10)* D25(GPIO14)* D27(CLK_SQUELCH_IN)* D28(TANA_0/NC)*; U56 A1(NC1)* A2(LED2_PHY3)* A3(JTAG_TMS)* A4(NC2)* A5(NC3)* A6(NC4)* B1(THERMDA)* B3(LED2_PHY2)* B6(JTAG_CLK)* B9(GPIO4)* B10(GPIO7)* B11(GPIO13)* B13(RCVRD_CLK0)* B14(TANA_1/NC)* C2(LED3_PHY0)* C4(LED2_PHY1)* C8(JTAG_DO)* C9(JTAG_DI)* C12(HSTST_P/NC)* C13(HSTST_N/NC)* C14(GPIO1)* C15(GPIO3)* C16(GPIO5)* C17(GPIO8)* C18(GPIO12)* C20(RCVRD_CLK1)* D2(LED2_PHY0)* D3(THERMDC_VSS)* D4(LED3_PHY1)* D6(LED3_PHY2)* D7(LED3_PHY3)* D19(GPIO0)* D20(GPIO2)* D21(GPIO6)* D22(GPIO9)* D23(GPIO11)* D24(GPIO10)* D25(GPIO14)* D27(CLK_SQUELCH_IN)* D28(TANA_0/NC)*; U57 A4(XRX2_DOUTP)* A5(XRX2_DOUTN)* C2(NC1)* C6(TX_CLKOUT1)* C7(GPIO1_1)* C10(TMS)* D3(GPIO1_2)* D10(TDI)* D11(RX_CLKOUT1)* E3(NC2)* E11(GPIO2_1)* F10(~{TRST})* F11(TCK)* G10(RX1_LOS)* G11(TDO)* H1(RX2_LOS)* J2(TX_CLKOUT2)* J3(RX_CLKOUT2)* J11(GPIO2_2)* L1(TX2_DOUTN)* L2(TX2_DOUTP)*; U59 2(RSVD1)* 4(RSVD2)* 22(I/O21)* 24(I/O11)* 27(~{TSCA})* 38(I/O12)* 40(I/O22)* 41(SWOUTZ)* 42(SWCMPZ)* 46(LFC2)* 59(RSVD3)* 62(RSVD4)* 63(RSVD5)* 64(RSVD6)* 65(RSVD7)* 66(RSVD8)* 68(RSVD9)* 70(RSVD10)* 72(RSVD11)* 73(RSVD12)* 74(RSVD13)* 75(RSVD14)* 76(RSVD15)* 78(RSVD16)* 80(RSVD17)*; U60 3*; U61 3*

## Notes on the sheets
sheet 18
- QSGMII PHY 1
- T1040 ONLY!
- REFCLK_SEL[1:0] = 00 for 125MHz clock
- PHY ADDR = 0x04~07
sheet 19
- QSGMII PHY 2
- T1040 ONLY!
- REFCLK_SEL[1:0] = 00 for 125MHz clock
- PHY ADDR = 0x08~0B
sheet 20
- QSGMII ETHERNET PORTs
- T1040 ONLY!
sheet 21
- 10G EDC PHY and SFP+ CONNECTOR
- T2081 ONLY!
- 100 ohms
  DIFF PAIRs
- 100 ohms
  DIFF PAIRs
- NO VIAs
- USE SFP+ RX LOS SIGNAL
- NO VIAs
- USE 1.8V IO
- PHY #2 UNUSED!
- PHY ADDR = 0x0C
- MDIO INTERFACE
- 1.8/2.5V IO
- I2C ADDR = 0x50,51
- FOR DEBUG ONLY!
- RX+/- AC COUPLING INSIDE THE MODULE
- TX+/- AC COUPLING INSIDE THE MODULE
sheet 22
- PCIe X1/X4 SLOT, MINI PCIe and SATA CONNECTORs
- MINI PCIe CONNECTOR
- PCIe x1/x4 SLOT
- T1040: PCIe x1
- T2081: PCIe x4
- 100 ohms
  DIFF PAIRs
- MINI PCIe CONNECTOR
- 100 ohms
  DIFF PAIRs
- 100 ohms
  DIFF PAIRs
- ON-BOARD SATA CONNECTOR
- T1040 ONLY!
- 100 ohms
  DIFF PAIRs
sheet 23
- POTS 1&2 INTERFACE
- T1040 ONLY!
